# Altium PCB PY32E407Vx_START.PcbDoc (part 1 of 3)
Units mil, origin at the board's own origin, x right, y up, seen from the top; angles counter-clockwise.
Board outline 5249.65 x 2929.09 mil, 4 copper layers (Top Layer, GND, POWER, Bottom Layer); 239 components, 235 nets, 934 pads, 637 vias.
Unrouted connection lines stored in the file: 84.
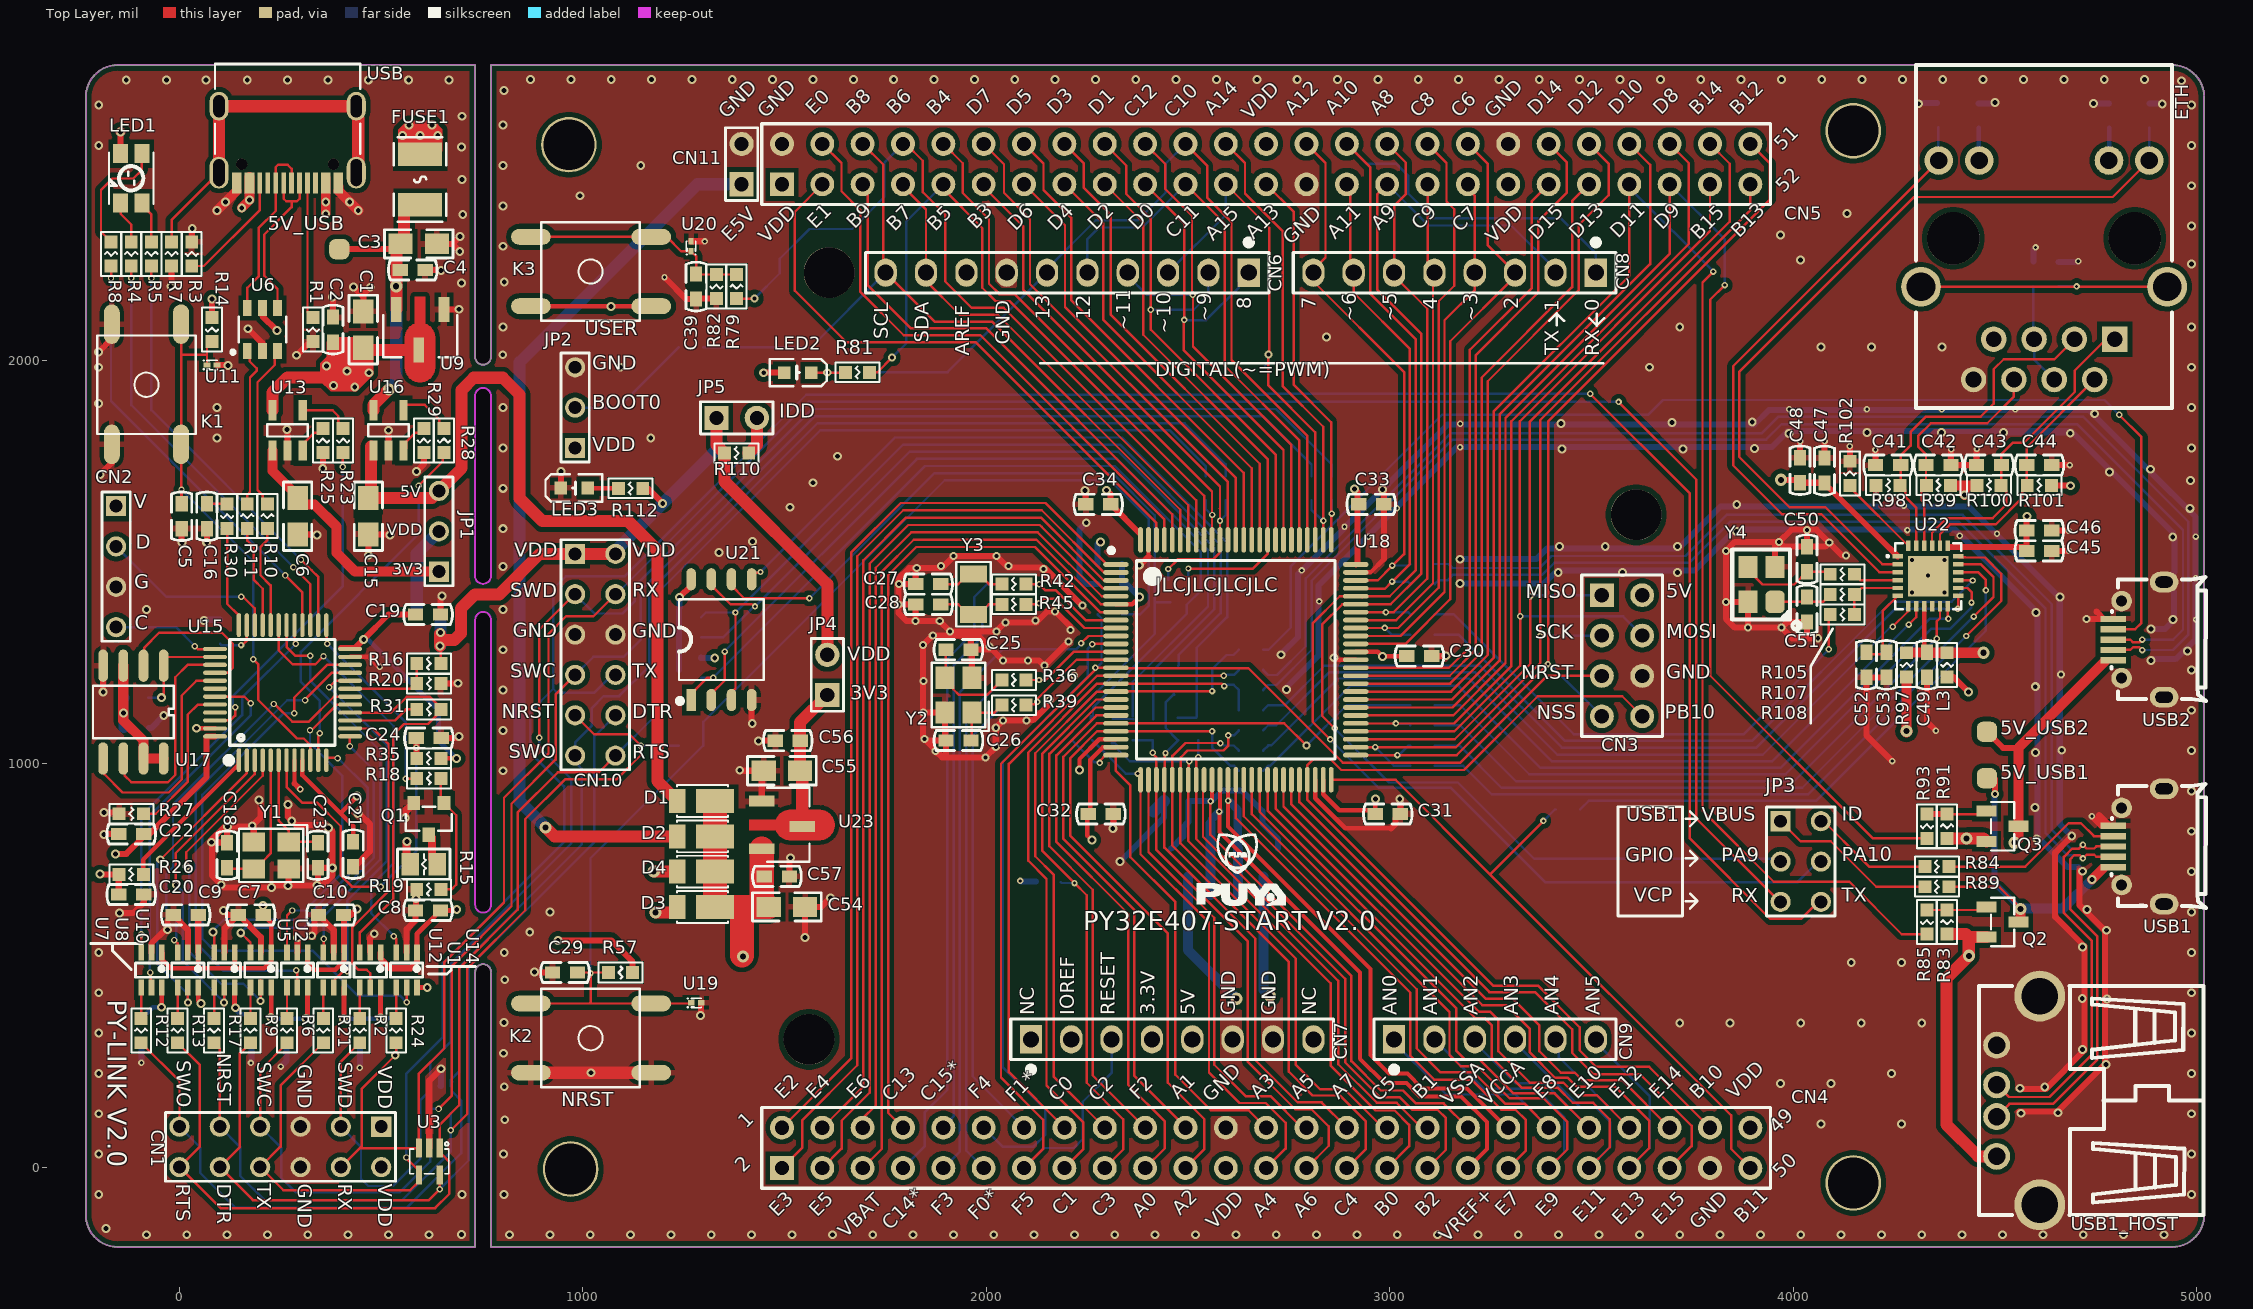
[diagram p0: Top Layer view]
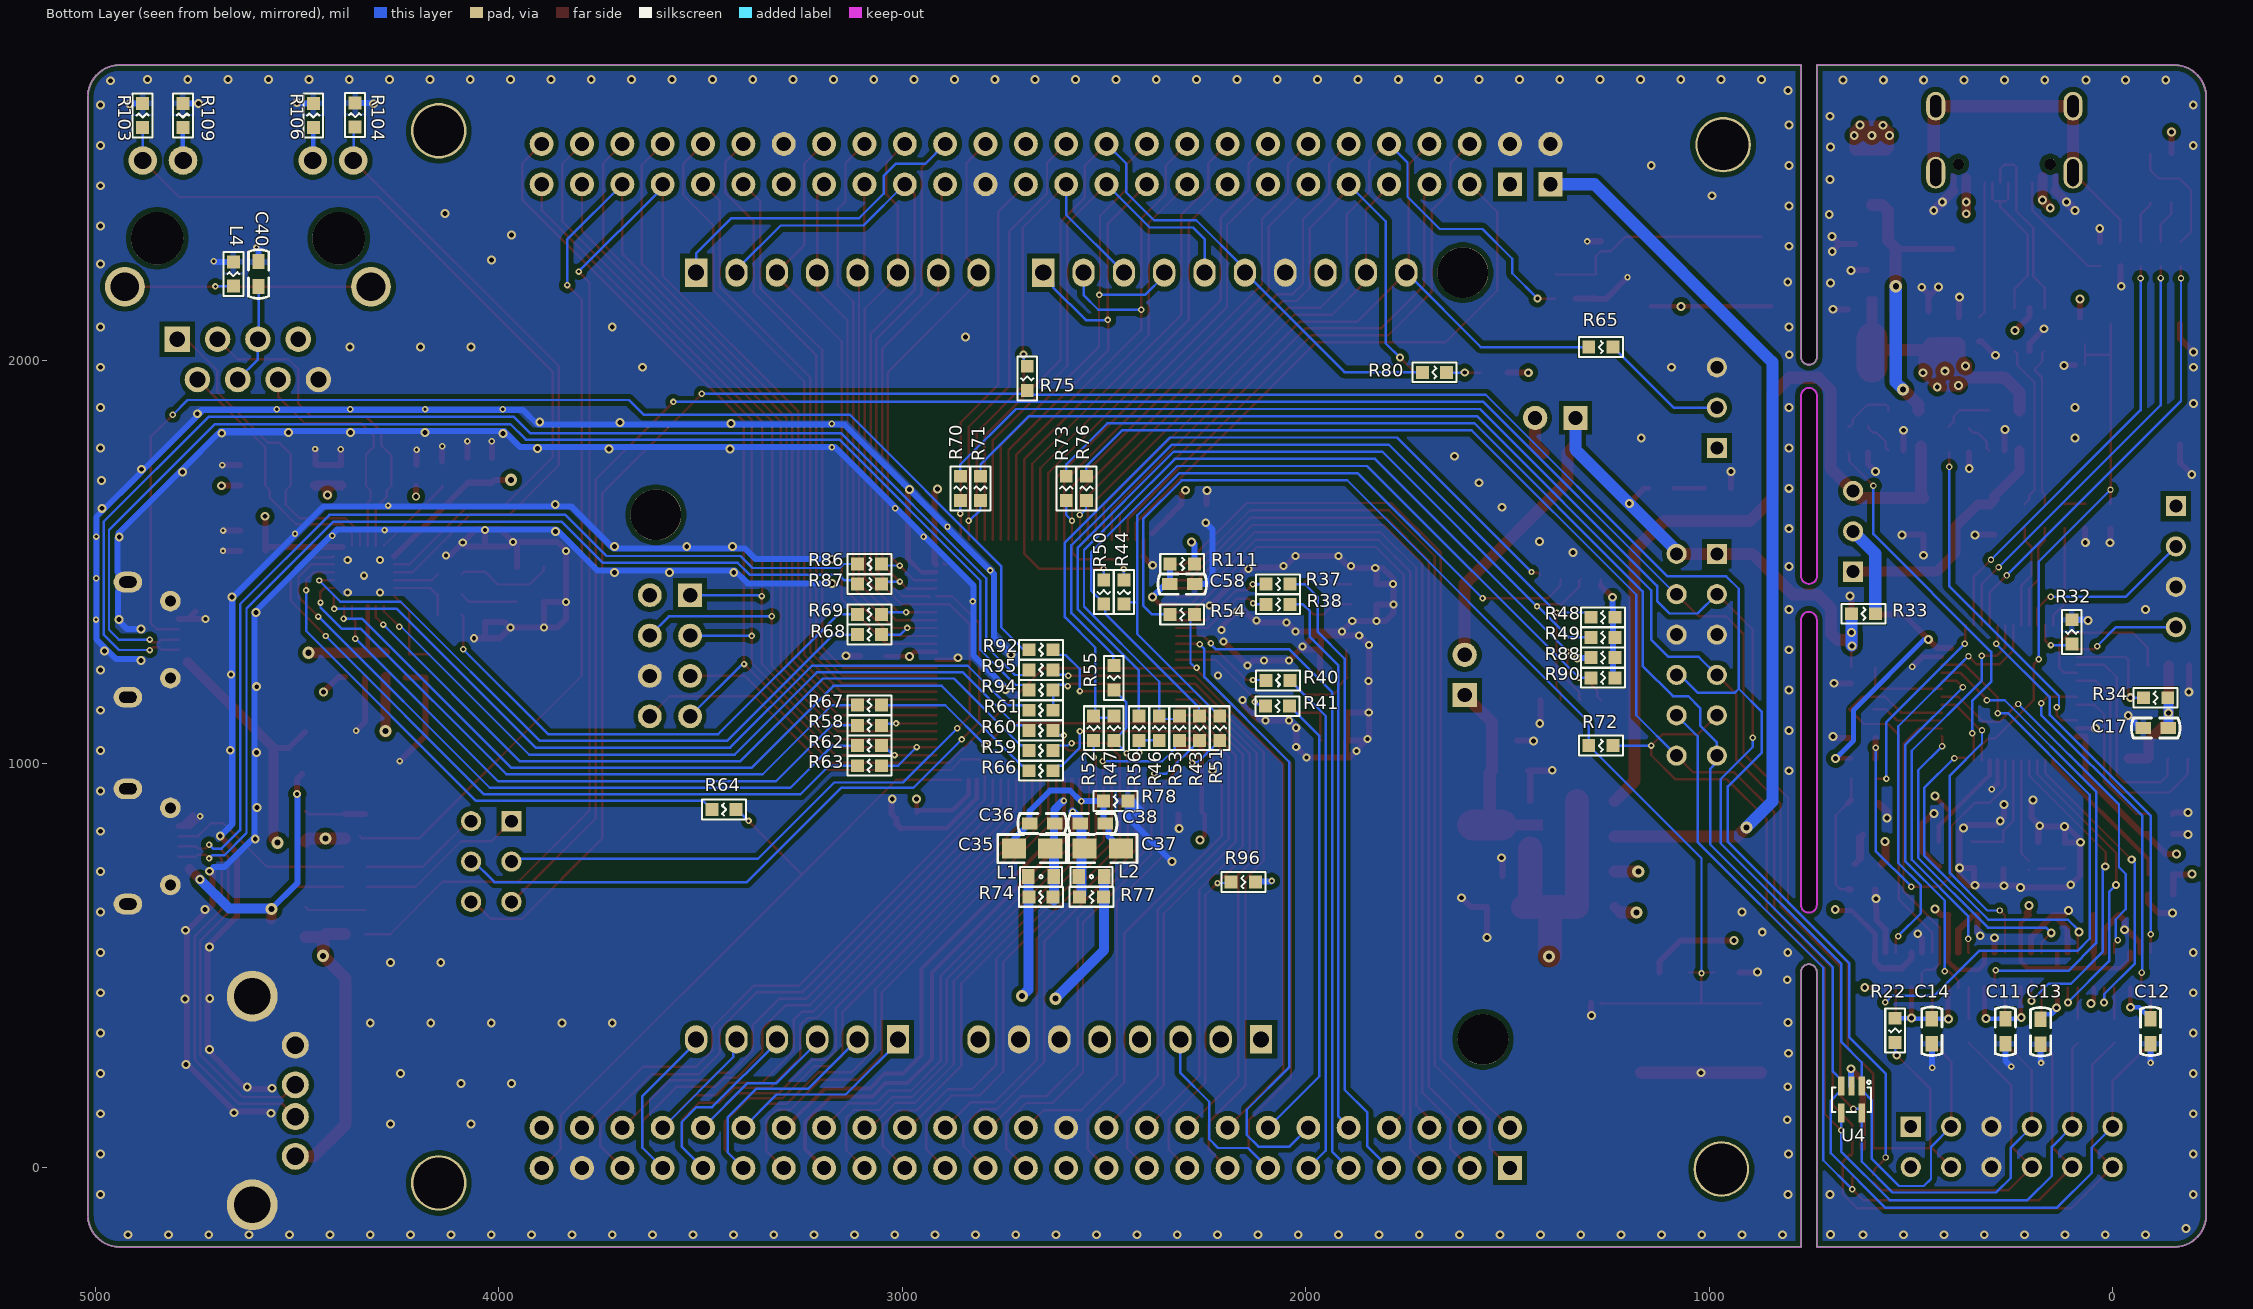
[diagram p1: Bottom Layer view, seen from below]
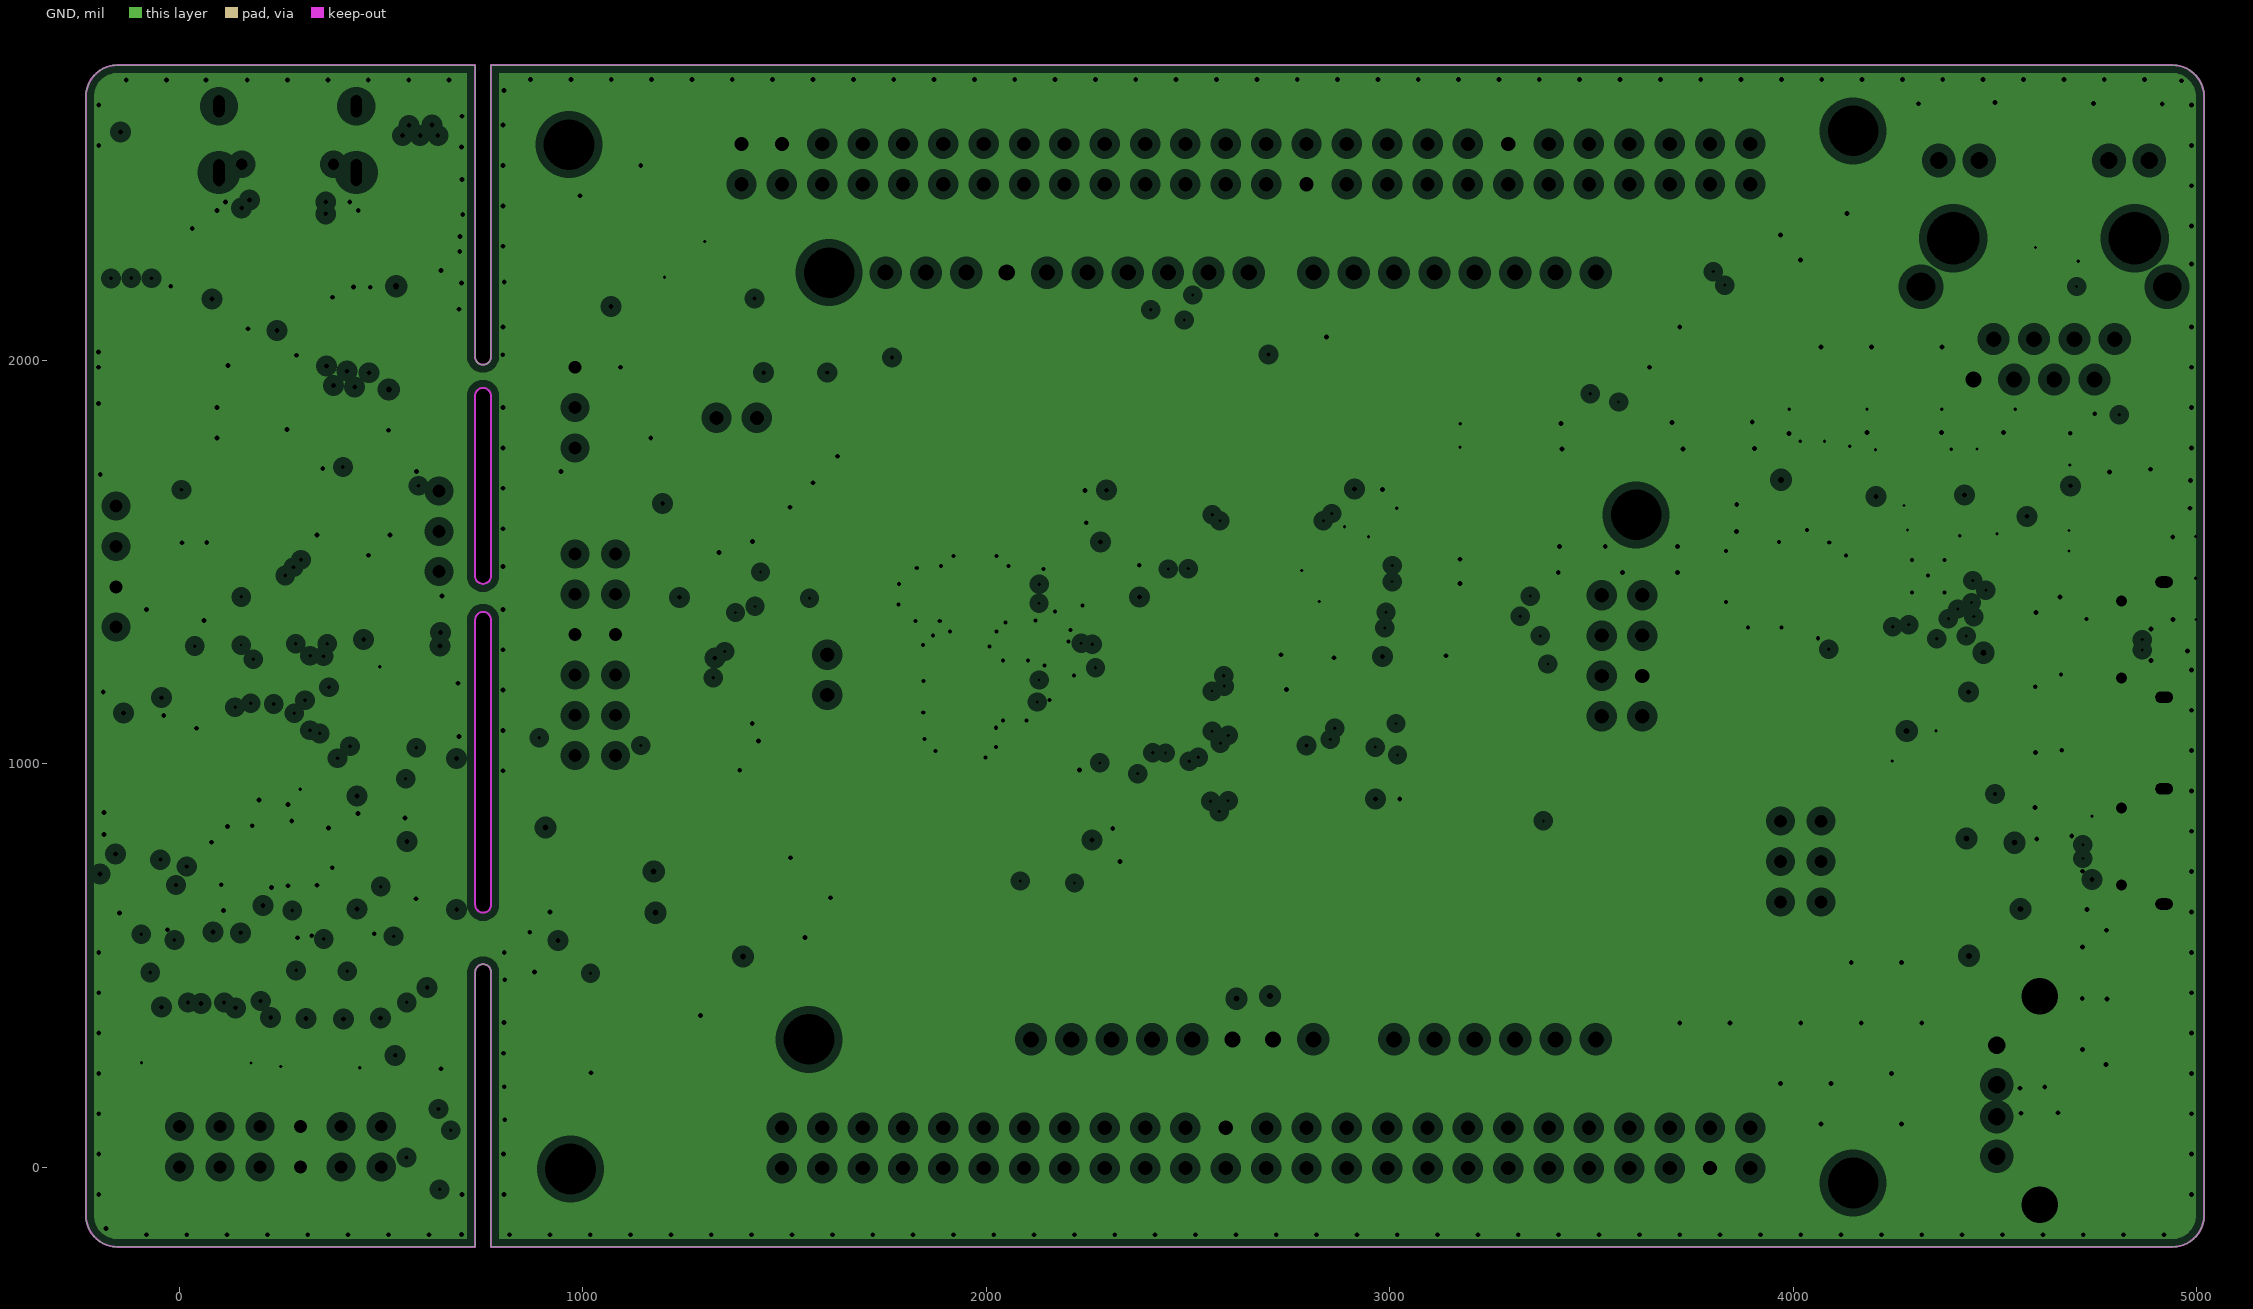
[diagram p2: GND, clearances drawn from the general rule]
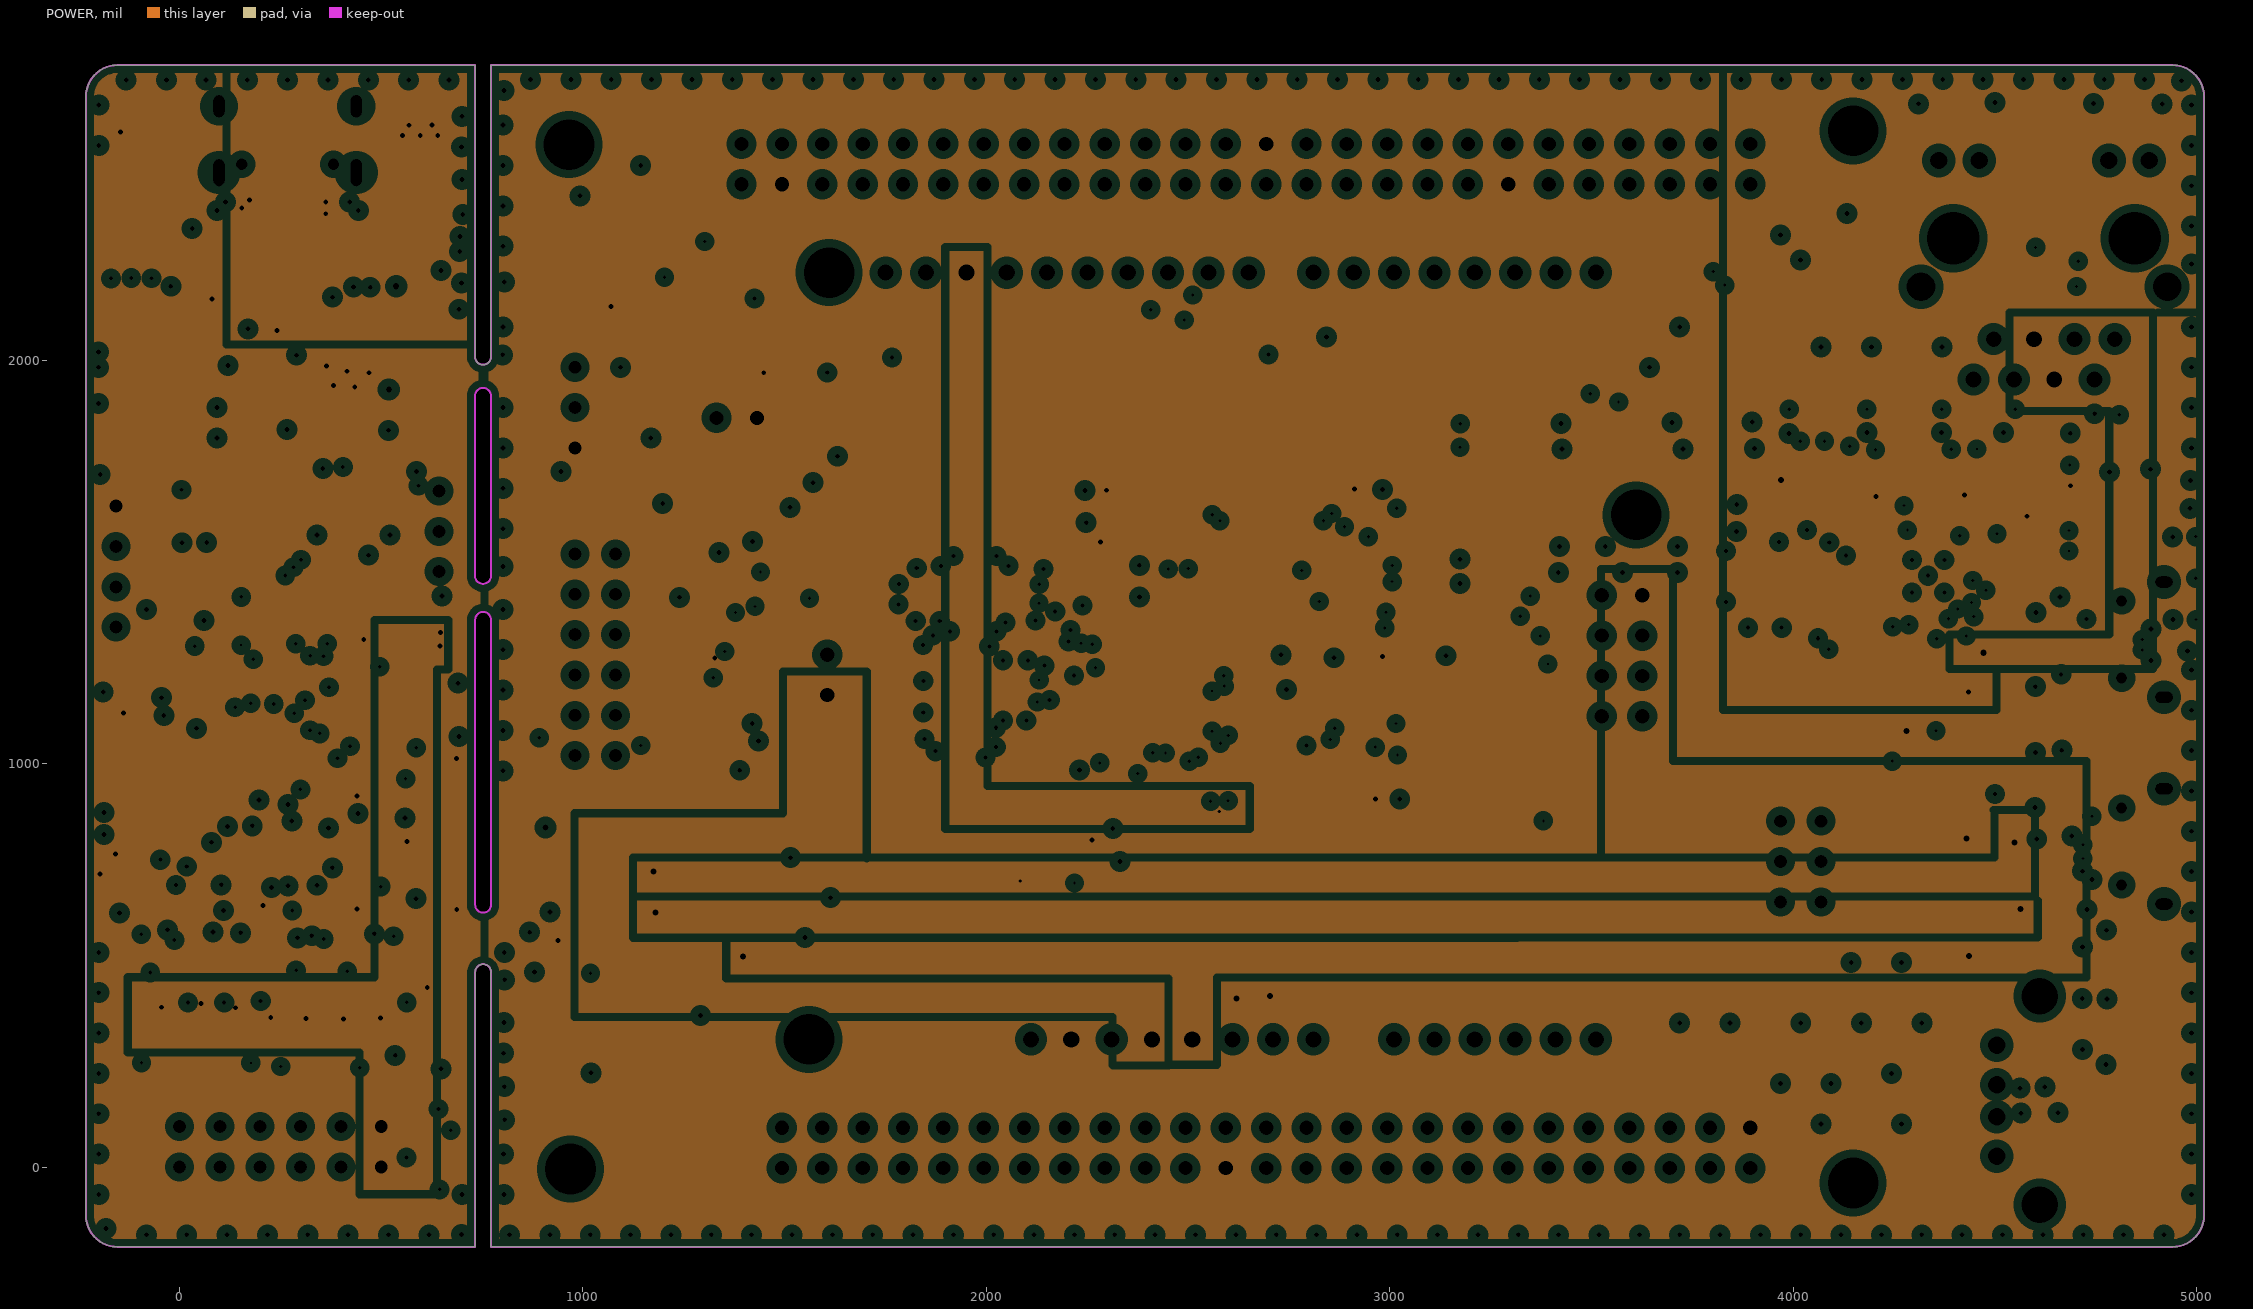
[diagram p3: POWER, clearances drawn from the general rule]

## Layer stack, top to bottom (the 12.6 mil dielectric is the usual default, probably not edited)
Top Solder: solder mask 0.4, Solder Resist, Dk 3.5
Top Layer: signal copper 1.4
Dielectric 2: prepreg 12.6, PP-006, Dk 4.1
GND: plane copper 1.378, net GND
Dielectric5: dielectric 12.6, FR-4, Dk 4.8
POWER: plane copper 1.378, net (Multiple Nets)
Dielectric4: dielectric 12.6, FR-4, Dk 4.8
Bottom Layer: signal copper 1.4
Bottom Solder: solder mask 0.4, Solder Resist, Dk 3.5

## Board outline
-153.26,-198 cw(c-153.26,-119.26) -232,-119.26 -232,2652.35 cw(c-153.26,2652.35) -153.26,2731.09 732.57,2731.09 732.57,2008.08 ccw(c752.25,2008.08) 771.94,2008.08 771.94,2731.09 4938.71,2731.09 cw(c4938.71,2652.35) 5017.45,2652.35 5017.65,2652.35 5017.65,-119.26 5017.61,-119.26 cw(c4938.87,-119.26) 4938.87,-198 772,-198 771.94,-198 771.94,483.05 772.29,483.05 ccw(c752.61,483.05) 732.92,483.05 732.57,483.05 732.57,-198
cut-out: 732.92,650.05 ccw(c752.61,650.05) 772.29,650.05 771.94,650.05 771.94,1356.05 772.29,1356.05 ccw(c752.61,1356.05) 732.92,1356.05 732.57,1357.05
cut-out: 732.57,1465.05 ccw(c752.25,1465.05) 771.94,1465.05 771.94,1911.05 ccw(c752.25,1911.05) 732.57,1911.05

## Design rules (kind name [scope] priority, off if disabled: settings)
Clearance [All] p1: gap=6 ignorepadtopadclearanceinfootprint=FALSE
ComponentClearance [All] p1 off: gap=10 collisioncheckmode=3 verticalgap=10 showdistances=FALSE
DiffPairsRouting DiffPairsRouting_2 [InDifferentialPair ('USB1')] p1: maxlimit=10 minlimit=10 mostfreqgap=10 toplayer_minwidth=15 toplayer_maxwidth=15 toplayer_prefwidth=15 bottomlayer_minwidth=15 bottomlayer_maxwidth=15 bottomlayer_prefwidth=15 maxuncoupledlength=500
DiffPairsRouting DiffPairsRouting_1 [InDifferentialPairClass('USB')] p2: maxlimit=10 minlimit=10 mostfreqgap=10 toplayer_minwidth=15 toplayer_maxwidth=15 toplayer_prefwidth=15 bottomlayer_minwidth=15 bottomlayer_maxwidth=15 bottomlayer_prefwidth=15 maxuncoupledlength=500
DiffPairsRouting DiffPair_DiffPairsRouting [All] p3: maxlimit=10 minlimit=10 mostfreqgap=10 toplayer_minwidth=15 toplayer_maxwidth=15 toplayer_prefwidth=15 bottomlayer_minwidth=15 bottomlayer_maxwidth=15 bottomlayer_prefwidth=15 maxuncoupledlength=500
DiffPairsRouting [All] p4: maxlimit=10 minlimit=10 mostfreqgap=10 toplayer_minwidth=15 toplayer_maxwidth=15 toplayer_prefwidth=15 bottomlayer_minwidth=15 bottomlayer_maxwidth=15 bottomlayer_prefwidth=15 maxuncoupledlength=500
HoleSize [All] p1: absolutevalues=TRUE maxlimit=300 minlimit=1 maxpercent=80.000 minpercent=20.000
HoleSize Testpoint [All] p2: absolutevalues=TRUE maxlimit=100 minlimit=1 maxpercent=80.000 minpercent=20.000
HoleSize TestPointUsage [All] p3: absolutevalues=TRUE maxlimit=100 minlimit=1 maxpercent=80.000 minpercent=20.000
MinimumSolderMaskSliver [All] p1: minsoldermaskwidth=0
PlaneClearance [All] p1: clearance=20
PlaneConnect [All] p1: planeconnectstyle=Direct reliefexpansion=20 reliefentries=4 reliefconductorwidth=10 reliefairgap=10
PolygonConnect "Polygon VIA" [IsVia] p1: connectstyle=Direct reliefconductorwidth=10 reliefentries=4 polygonreliefangle="90 Angle" airgapwidth=10
PolygonConnect [All] p2: thpad.connectstyle=Direct thpad.reliefconductorwidth=10 thpad.reliefentries=4 thpad.polygonreliefangle="90 Angle" thpad.airgapwidth=10 smdpad.connectstyle=Relief smdpad.reliefconductorwidth=15 smdpad.reliefentries=4 smdpad.polygonreliefangle="90 Angle" smdpad.airgapwidth=10 via.connectstyle=Direct via.reliefconductorwidth=10 via.reliefentries=4 via.polygonreliefangle="90 Angle" via.airgapwidth=10
RoutingVias [All] p1: holewidth=20 width=40 viastyle="Through Hole" minholewidth=20 minwidth=40 maxholewidth=20 maxwidth=40
SilkToSilkClearance [All] p1: silktosilkclearance=0
SilkToSolderMaskClearance [IsPad] p1: minsilkscreentomaskgap=0 clearancetoexposedcopper=TRUE
SolderMaskExpansion [All] p1: expansion=4 istentingtop=FALSE
SupplyNets "Schematic Supply Nets_18" [InNet('E_5V')] p1: voltage=0.000
SupplyNets "Schematic Supply Nets_17" [InNet('5V_USB1_START')] p2: voltage=0.000
SupplyNets "Schematic Supply Nets_16" [InNet('ETH_VDDA')] p3: voltage=0.000
SupplyNets "Schematic Supply Nets_15" [InNet('VCCA')] p4: voltage=0.000
SupplyNets "Schematic Supply Nets_14" [InNet('3V3')] p5: voltage=0.000
SupplyNets "Schematic Supply Nets_13" [InNet('VDD')] p6: voltage=0.000
SupplyNets "Schematic Supply Nets_12" [InNet('TVDD')] p7: voltage=0.000
SupplyNets "Schematic Supply Nets_11" [InNet('VREF+')] p8: voltage=0.000
SupplyNets "Schematic Supply Nets_10" [InNet('GND')] p9: voltage=0.000
SupplyNets "Schematic Supply Nets_9" [InNet('VBAT')] p10: voltage=0.000
SupplyNets "Schematic Supply Nets_8" [InNet('5V_USB_CHGR')] p11: voltage=0.000
SupplyNets "Schematic Supply Nets_7" [InNet('5V_USB2_START')] p12: voltage=0.000
SupplyNets "Schematic Supply Nets_6" [InNet('5V')] p13: voltage=0.000
SupplyNets "Schematic Supply Nets_5" [InNet('3V3_USB_PYLK')] p14: voltage=0.000
SupplyNets "Schematic Supply Nets_4" [InNet('VDD_FLASH')] p15: voltage=0.000
SupplyNets "Schematic Supply Nets_3" [InNet('3V3_PYLK')] p16: voltage=0.000
SupplyNets "Schematic Supply Nets_2" [InNet('5V_USB_PYLK')] p17: voltage=0.000
SupplyNets "Schematic Supply Nets_1" [InNet('VSSA')] p18: voltage=0.000
SupplyNets "Schematic Supply Nets" [InNet('ETH_VDD')] p19: voltage=0.000
Width [All] p1: maxlimit=80 minlimit=6 preferedwidth=6
22 further rules are at their usual default settings.

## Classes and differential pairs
component class Designator: C39 K3 LED2 Q2 Q3 R82 R83 R84 R85 R86 R87 R88 R89 R90 R91 R92 R93 R94 R95 R96 U20 U21 USB1 USB1_HOST USB2
net class PF[0..5]: PF0 PF1 PF2 PF3 PF4 PF5
net class PE[0..15]: PE0 PE1 PE2 PE3 PE4 PE5 PE6 PE7 PE8 PE9 PE10 PE11 PE12 PE13 PE14 PE15
net class PD[0..15]: PD0 PD1 PD2 PD3 PD4 PD5 PD6 PD7 PD8 PD9 PD10 PD11 PD12 PD13 PD14 PD15
net class PC[0..15]: PC0 PC1 PC2 PC3 PC4 PC5 PC6 PC7 PC8 PC9 PC10 PC11 PC12 PC13 PC14 PC15
net class PB[0..15]: PB0 PB1 PB2 PB3 PB4 PB5 PB6 PB7 PB8 PB9 PB10 PB11 PB12 PB13 PB14 PB15
net class PA[0..15]: PA0 PA1 PA2 PA3 PA4 PA5 PA6 PA7 PA8 PA9 PA10 PA11 PA12 PA13 PA14 PA15

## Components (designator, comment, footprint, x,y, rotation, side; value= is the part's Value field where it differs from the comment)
5V_USB "TP_SIN" TP_SIN 396.1,2274.79 r0 top
5V_USB1 "TP_SIN" TP_SIN 4479.3,963.69 r0 top
5V_USB2 "TP_SIN" TP_SIN 4479.3,1078.69 r0 top
C1 "10uF" C0805 455.5,2075.5 r270 top
C2 "100nF" C0603 380.5,2075.5 r270 top
C3 "10uF" C0805 593,2288 r180 top
C4 "100nF" C0603 578.1,2223.2 r180 top
C5 "100nF" C0603 5.5,1613 r90 top
C6 "10uF" C0805 293,1613 r90 top
C7 "100nF" C0603 176.6,624.9 r0 top value=104
C8 "100nF" C0603 616,636.09 r0 top value=104
C9 "100nF" C0603 15.3,624.9 r0 top value=104
C10 "100nF" C0603 375.5,624.9 r0 top value=104
C11 "100nF" C0603 265.7,336.7 r90 bottom value=104
C12 "100nF" C0603 -94.3,336.6 r90 bottom value=104
C13 "100nF" C0603 178.2,335.3 r90 bottom value=104
C14 "100nF" C0603 447.9,336.7 r90 bottom value=104
C15 "10uF" C0805 468,1613 r90 top
C16 "100nF" C0603 68,1613 r90 top
C17 "100nF" C0603 -107,1088 r180 bottom value=104
C18 "22pF" C0603 118,772.6 r270 top
C19 "100nF" C0603 616,1369.3 r180 top value=104
C20 "100nF" C0603 -119.5,675.5 r180 top value=104
C21 "100nF" C0603 430.5,775.5 r90 top value=104
C22 "100nF" C0603 -119.5,825.5 r0 top value=104
C23 "22pF" C0603 343,772.6 r90 top
C24 "100nF" C0603 618,1063 r180 top value=104
C25 "22pF" C0603 1930.5,1282.09 r180 top
C26 "22pF" C0603 1930.5,1057.09 r0 top
C27 "22pF" C0603 1855.5,1444.59 r0 top
C28 "22pF" C0603 1855.5,1394.59 r0 top
C29 "100nF" C0603 955.5,482.09 r0 top
C30 "100nF" C0603 3072.8,1266.29 r180 top
C31 "100nF" C0603 2994.61,875.01 r180 top
C32 "100nF" C0603 2283.54,875.01 r180 top
C33 "100nF" C0603 2953.6,1642.49 r180 top
C34 "100nF" C0603 2276.7,1642.49 r0 top
C35 "1uF" C0805 2677.6,789.09 r180 bottom
C36 "100nF" C0603 2652.6,851.59 r180 bottom
C37 "1uF" C0805 2502.6,789.09 r0 bottom
C38 "100nF" C0603 2527.6,851.59 r0 bottom
C39 "100nF" C0603 1280.5,2182.09 r90 top
C40 "100nF" C0603 4594.5,2213.09 r270 bottom
C41 "NC/10pF" C0603 4234.4,1739.59 r0 top
C42 "NC/10pF" C0603 4359.4,1739.59 r180 top
C43 "NC/10pF" C0603 4484.4,1739.59 r0 top
C44 "NC/10pF" C0603 4609.4,1739.59 r180 top
C45 "100nF" C0603 4609,1527.09 r180 top
C46 "100nF" C0603 4609,1577.09 r180 top
C47 "10uF" C0603 4076.7,1726.19 r270 top
C48 "100nF" C0603 4016.2,1726.89 r270 top
C49 "100nF" C0603 4330.5,1244.59 r90 top
C50 "22pF" C0603 4033.5,1506.59 r90 top
C51 "22pF" C0603 4033.5,1381.59 r90 top
C52 "10uF" C0603 4180.5,1244.59 r90 top
C53 "100nF" C0603 4230.5,1244.59 r90 top
C54 "10uF" C0805 1505.5,644.59 r180 top
C55 "10uF" C0805 1493,982.09 r0 top
C56 "0.1uF/50V" C0603CAP 1476.4,1056.59 r90 top
C57 "0.1uF/50V" C0603CAP 1511.6,720.29 r270 top value=2.2uF
C58 "100nF" C0603 2305.5,1444.59 r0 bottom
CN1 "CON6x2" CON6X2 500,0 r270 top locked
CN2 "CON4" CON4 -157,1638 r270 top
CN3 "Header 4X2" HDR2X4 3525.12,1417.14 r270 top locked
CN4 "Header 25X2" HDR2X25 1493.11,-2.45 r0 top locked
CN5 "Header 25X2" HDR2X25 1493.11,2435.55 r0 top locked
CN6 "Header 10" 1*10P_FEMALE 2650.11,2216.55 r180 top locked
CN7 "Header 8" 1*8P_FEMALE 2110.11,316.55 r0 top locked
CN8 "Header 8" 1*8P_FEMALE 3510.11,2216.55 r180 top locked
CN9 "Header 6" 1*6P_FEMALE 3010.11,316.55 r0 top locked
CN10 "CON6x2" CON6X2 1080.5,1519.59 r0 top locked
CN11 "CON2" CON2 1393.11,2435.55 r90 top locked
D1 "DFLS130L-7" POWERDI-123_L2.8-W1.8-LS3.7-RD 1280.5,907.09 r180 top
D2 "DFLS130L-7" POWERDI-123_L2.8-W1.8-LS3.7-RD 1280.5,819.59 r180 top
D3 "DFLS130L-7" POWERDI-123_L2.8-W1.8-LS3.7-RD 1280.5,644.59 r180 top
D4 "DFLS130L-7" POWERDI-123_L2.8-W1.8-LS3.7-RD 1280.5,732.09 r180 top
ETH "HR911105A" RJ45-TH_HR911105A 4621,2223.09 r180 top locked
FUSE1 "BSMD1206-050-6V" SDM1210P005TF 618,2450.5 r270 top
JP1 "CON3" CON3 643,1475.5 r90 top
JP2 "CON3" CON3 980.5,1782.09 r90 top
JP3 "CON3x2" CON3x2 4068,857.09 r0 top
JP4 "CON2" CON2 1605.5,1169.59 r90 top
JP5 "CON2" CON2 1330.89,1856.71 r0 top
K1 "1TS002B-2600-5001_key" SWITCH -82,1938 r90 top
K2 "1TS002B-2600-5001_key" SWITCH 1018,319.59 r0 top locked
K3 "1TS002B-2600-5001_key" SWITCH 1018,2219.59 r0 top locked
L1 "BEAD" L0603 2655.5,719.59 r180 bottom value=600R@100MHz
L2 "BEAD" L0603 2530.5,719.59 r0 bottom value=600R@100MHz
L3 "330@100MHz" R0603 4380.5,1244.59 r90 top
L4 "330@100MHz" R0603 4657,2213.09 r270 bottom
LED1 "MHPA3528RGBCT" LED-ARRAY-SMD_4P-L3.5-W2.8-TL -119.5,2450.5 r90 top
LED2 "GREEN" 0603_LED 1518,1969.59 r180 top
LED3 "RED" 0603_LED 993,1682.09 r0 top
Q1 "2302" SOT23 618,863 r0 top value=SI2302
Q2 "SI2301" SOT-23-3_L2.9-W1.3-P1.90-LS2.4-BR 4518,607.09 r180 top
Q3 "SI2301" SOT-23-3_L2.9-W1.3-P1.90-LS2.4-BR 4518,844.59 r180 top
R1 "5.1K" R0603 330.5,2075.5 r90 top
R2 "27R" R0603 446.71,338 r270 top
R3 "5.1K" R0603 30.5,2263 r90 top
R4 "680R" R0603 -119.5,2263 r270 top
R5 "680R" R0603 -69.5,2263 r270 top
R6 "27R" R0603 266.14,338 r270 top
R7 "1M" R0603 -19.5,2263 r270 top
R8 "680R" R0603 -169.5,2263 r270 top
R9 "27R" R0603 175.86,338 r270 top
R10 "27R" R0603 218,1613 r270 top
R11 "27R" R0603 168,1613 r270 top
R12 "27R" R0603 -95,338 r270 top
R13 "27R" R0603 -4.71,338 r270 top
R14 "10K" R0603 80.5,2075.5 r90 top
R15 "100R" R0805 605.5,750.5 r180 top
R16 "20K" R0603 618,1248 r0 top
R17 "27R" R0603 85.57,338 r270 top
R18 "100R" R0603 618,963 r180 top
R19 "100K" R0603 618,688 r0 top
R20 "10K" R0603 618,1198 r180 top
R21 "27R" R0603 356.43,338 r270 top
R22 "4.7K" R0603 538.7,338.7 r90 bottom
R23 "4.7K" R0603 405.5,1800.5 r90 top
R24 "27R" R0603 537,338 r270 top
R25 "16K" R0603 355.5,1800.5 r90 top
R26 "0R/NC" R0603 -119.5,725.5 r0 top
R27 "10K" R0603 -119.5,875.5 r180 top
R28 "4.7K" R0603 655.5,1800.5 r90 top
R29 "16K" R0603 605.5,1800.5 r90 top
R30 "0R/NC" R0603 118,1613 r90 top
R31 "100R" R0603 618,1134.09 r180 top
R32 "0R/NC" R0603 100.8,1326.39 r90 bottom
R33 "0R" R0603 617.1,1371.3 r0 bottom
R34 "100K" R0603 -107,1163 r180 bottom
R35 "10K" R0603 618,1013 r0 top
R36 "0R" R0603 2068,1207.09 r0 top
R37 "0R" R0603 2068,1444.59 r0 bottom
R38 "0R" R0603 2068,1394.59 r0 bottom
R39 "0R" R0603 2068,1144.59 r0 top
R40 "0R" R0603 2068.2,1205.99 r0 bottom
R41 "0R" R0603 2069.3,1142.19 r0 bottom
R42 "0R" R0603 2068,1444.59 r0 top
R43 "0R" R0603 2262.5,1087.5 r270 bottom
R44 "0R" R0603 2450,1425 r90 bottom
R45 "0R" R0603 2068,1394.59 r0 top
R46 "0R" R0603 2362.5,1087.5 r270 bottom
R47 "0R" R0603 2475,1087.5 r270 bottom
R48 "0R/NC" R0603 1262.5,1362.5 r180 bottom
R49 "0R/NC" R0603 1262.5,1312.5 r180 bottom
R50 "0R" R0603 2500,1425 r90 bottom
R51 "0R" R0603 2212.5,1087.5 r270 bottom
R52 "0R" R0603 2525,1087.5 r270 bottom
R53 "0R" R0603 2312.5,1087.5 r270 bottom
R54 "0R" R0603 2305.5,1369.59 r180 bottom
R55 "0R" R0603 2475,1212.5 r270 bottom
R56 "0R" R0603 2412.5,1087.5 r270 bottom
R57 "10K" R0603 1093,482.09 r180 top
R58 "0R" R0603 3080.5,1094.59 r180 bottom
R59 "0R" R0603 2655.5,1032.09 r180 bottom
R60 "0R" R0603 2655.5,1082.09 r180 bottom
R61 "0R" R0603 2655.5,1132.09 r180 bottom
R62 "0R" R0603 3080.5,1044.59 r180 bottom
R63 "0R" R0603 3080.5,994.59 r180 bottom
R64 "0R" R0603 3441.05,886.09 r180 bottom
R65 "10K" R0603 1268,2032.09 r0 bottom
R66 "0R" R0603 2655.5,982.09 r180 bottom
R67 "0R" R0603 3080.5,1144.59 r180 bottom
R68 "0R" R0603 3080.5,1319.59 r180 bottom
R69 "0R" R0603 3080.5,1369.59 r180 bottom
R70 "0R" R0603 2855.5,1682.09 r270 bottom
R71 "0R" R0603 2805.5,1682.09 r270 bottom
R72 "0R" R0603 1268,1044.59 r0 bottom
R73 "0R" R0603 2593,1682.09 r270 bottom
R74 "0R/NC" R0603 2655.5,669.59 r180 bottom
R75 "0R" R0603 2689.6,1954.69 r90 bottom
R76 "0R" R0603 2543,1682.09 r270 bottom
R77 "0R/NC" R0603 2530.5,669.59 r0 bottom
R78 "0R" R0603 2470.4,907.19 r180 bottom
R79 "0R" R0603 1380.5,2182.09 r270 top
R80 "680R/NC" R0603 1680.5,1969.59 r0 bottom
R81 "680R" R0603 1680.5,1969.59 r0 top
R82 "1.5K" R0603 1330.5,2182.09 r90 top
R83 "10K" R0603 4380.5,607.09 r270 top
R84 "1K" R0603 4355.5,744.59 r0 top
R85 "470R" R0603 4330.5,607.09 r90 top
R86 "22R" R0603 3080.5,1494.59 r0 bottom
R87 "22R" R0603 3080.5,1444.59 r0 bottom
R88 "0R" R0603 1262.5,1262.5 r180 bottom
R89 "10K" R0603 4355.5,694.59 r0 top
R90 "100K" R0603 1262.5,1212.5 r180 bottom
R91 "10K" R0603 4380.5,844.59 r270 top
R92 "1K" R0603 2655.5,1282.09 r0 bottom
R93 "470R" R0603 4330.5,844.59 r90 top
R94 "22R" R0603 2655.5,1182.09 r0 bottom
R95 "22R" R0603 2655.5,1232.09 r0 bottom
R96 "10K" R0603 2154.2,706.19 r180 bottom
R97 "0R" RES0603 4280.5,1244.59 r90 top
R98 "49.9R" R0603 4234.4,1689.59 r180 top
R99 "49.9R" R0603 4359.4,1689.59 r0 top
R100 "49.9R" R0603 4484.4,1689.59 r180 top
R101 "49.9R" R0603 4609.4,1689.59 r0 top
R102 "12.1K" R0603 4139.7,1719.09 r90 top
R103 "4.7K" R0603 4882,2606.09 r270 bottom
R104 "4.7K" R0603 4355.5,2607.09 r270 bottom
R105 "0R" R0603 4121,1469.09 r0 top
R106 "270" R0603 4459,2606.09 r270 bottom
R107 "0R" R0603 4121,1419.09 r0 top
R108 "0R" R0603 4121,1369.09 r180 top
R109 "270" R0603 4782,2606.09 r270 bottom
R110 "0R" R0603 1380.89,1769.21 r0 top
R111 "0R" R0603 2305.5,1494.59 r0 bottom
R112 "680R" R0603 1118,1682.09 r0 top
U1 "74LVC1T45DW" SOT363 472.69,488.04 r180 top
U2 "74LVC1T45DW" SOT363 292,488.04 r180 top
U3 "ESD_6V1" ESD_SOT323-5L 619,14 r180 top value=ESDALC6V1W5
U4 "ESD_6V1" ESD_SOT323-5L 647,167 r0 bottom value=ESDALC6V1W5
U5 "74LVC1T45DW" SOT363 201.66,488.04 r180 top
U6 "USBLC6-2SC6" SOT23-6 205.5,2075.5 r180 top
U7 "74LVC1T45DW" SOT363 -69.37,488.04 r180 top
U8 "74LVC1T45DW" SOT363 20.97,488.04 r180 top
U9 "LM1117-3.3" LM1117-3.3 655.5,2125.5 r90 top
U10 "74LVC1T45DW" SOT363 111.31,488.04 r180 top
U11 "ESD-TRANSIL" ESD_ST0201 80.5,1988 r0 top value=ESDALC6V1-1U2
U12 "74LVC1T45DW" SOT363 382.34,488.04 r180 top
U13 "MT9700" SOT23-5 268,1825.5 r0 top
U14 "74LVC1T45DW" SOT363 563.03,488.04 r180 top
U15 "PY32F072C1xT" LQFP-48_L7.0-W7.0-P0.50-LS9.0-BL 255.5,1175.69 r0 top locked
U16 "MT9700" SOT23-5 518,1825.5 r0 top
U17 "P25Q64H" SOP-8P -114.3,1127.5 r180 top value=SST25VF020B
U18 "PY32E407Vx" LQFP-100_L14.0-W14.0-P0.50-LS16.0-BL 2618,1257.09 r270 top locked
U19 "ESD-TRANSIL" ESD_ST0201 1280.5,407.09 r0 top value=ESDALC6V1-1U2
U20 "ESD-TRANSIL" ESD_ST0201 1268,2282.09 r90 top value=ESDALC6V1-1U2
U21 "P25Q128H" SOP8W_L 1343,1307.09 r90 top locked
U22 "LAN8720A-CP-TR" QFN-24_L4.0-W4.0-P0.50-BL-EP2.6 4333.5,1464.59 r270 top
U23 "LM1117-3.3" LM1117-3.3 1443,907.09 r180 top
USB "KH-TYPE-C-16P" USB-C-SMD_KH-TYPE-C-16P 268,2534 r180 top
USB1 "Micro-B" MICRO-USB-SMD_MICROXNJ 4855.5,794.59 r90 top locked
USB1_HOST "Type-A" USB-A-TH_AF-WJDG 4557,165.09 r90 top locked
USB2 "Micro-B" MICRO-USB-SMD_MICROXNJ 4855.5,1307.09 r90 top locked
Y1 "24MHz" CRYSTAL-SMD_4P-L3.2-W2.5-BL 227.3,772.6 r180 top
Y2 "24MHz" CRYSTAL-SMD_4P-L3.2-W2.5-BL 1930.5,1169.59 r90 top
Y3 "32.768KHz" CRYSTAL-SMD_L3.2-W1.5-1 1968,1419.59 r90 top value=32.768kHz
Y4 "25MHz" SMD-3225_4P 3921,1444.09 r90 top

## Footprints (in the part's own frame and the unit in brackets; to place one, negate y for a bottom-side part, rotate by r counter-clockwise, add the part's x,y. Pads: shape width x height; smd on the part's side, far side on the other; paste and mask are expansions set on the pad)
1*6P_FEMALE [mil]
  rect 55x70 hole 40: 1(0,0)
  oval 55x70 hole 40: 2(100,0) 3(200,0) 4(300,0) 5(400,0) 6(500,0)
  silkscreen extent -50,-82 550,50
1*8P_FEMALE [mil]
  rect 55x70 hole 40: 1(0,0)
  oval 55x70 hole 40: 2(100,0) 3(200,0) 4(300,0) 5(400,0) 6(500,0) 7(600,0) 8(700,0)
  silkscreen extent -50,-82 750,50
1*10P_FEMALE [mil]
  rect 55x70 hole 40: 1(0,0)
  oval 55x70 hole 40: 2(100,0) 3(200,0) 4(300,0) 5(400,0) 6(500,0) 7(600,0) 8(700,0) 9(800,0) 10(900,0)
  silkscreen extent -50,-82 950,50
0603_LED [mil]
  rect 31.5x31.5 smd: 1(19,1) 2(-48,1)
  silkscreen extent -86,-33 55,35
C0603 [mil]
  rect 38x30 smd: 1(-31,0) 2(31,0)
  silkscreen extent -60,-25 60,25
C0603CAP [mil]
  rect 30x38 smd: 1(0,0) 2(0,-62)
  silkscreen extent -25,-91 25,29
C0805 [mil]
  rect 60x50 smd: 1(-45,0) 2(45,0)
  silkscreen extent -85,-35 85,35
CON2 [mil]
  rect 60x60 hole 35: 1(0,0)
  round 60 hole 35: 2(100,0)
  silkscreen extent -40,-40 140,40
CON3 [mil]
  rect 50x50 hole 32: 1(0,0)
  round 50 hole 32: 2(100,0) 3(200,0)
  silkscreen extent -35,-35 235,35
CON3x2 [mil]
  rect 50x50 hole 32: 1(-100,0)
  round 50 hole 32: 2(0,0) 3(-100,-100) 4(0,-100) 5(-100,-200) 6(0,-200)
  silkscreen extent -135,-235 35,35
CON4 [mil]
  rect 50x50 hole 32: 1(0,0)
  round 50 hole 32: 2(100,0) 3(200,0) 4(300,0)
  silkscreen extent -35,-35 335,35
CON6X2 [mil]
  rect 50x50 hole 32: 1(-100,0)
  round 50 hole 32: 2(0,0) 3(-100,-100) 4(0,-100) 5(-100,-200) 6(0,-200) 7(-100,-300) 8(0,-300) 9(-100,-400) 10(0,-400) 11(-100,-500) 12(0,-500)
  silkscreen extent -135,-535 35,35
CRYSTAL-SMD_4P-L3.2-W2.5-BL [mm]
  rect 1.4x1.2 smd: 1(-1.1,-0.85) 2(1.1,-0.85) 3(1.1,0.85) 4(-1.1,0.85)
  silkscreen extent -2.26,-1.91 2.03,1.68
CRYSTAL-SMD_L3.2-W1.5-1 [mm]
  rect 1.05x1.7 smd: 1(-1.275,0) 2(1.275,0)
  silkscreen extent -2.03,-1.08 2.03,1.08
ESD_SOT323-5L [mm]
  rect 0.4x1.2 smd mask+0.05: 1(-0.65,-0.85) 2(0,-0.85) 3(0.65,-0.85) 4(0.65,0.85) 5(-0.65,0.85)
  silkscreen extent -1.23,-1.21 1.23,0.77, body extent -1.15,-1.05 1.15,1.05, height 1.1
ESD_ST0201 [mm]
  rect 0.425x0.33 smd mask+0.05: 1(-0.312,0) 2(0.312,0)
  silkscreen extent -0.55,-0.3 0.33,0.3, body extent -0.34,-0.18 0.34,0.18, height 0.34
HDR2X4 [mm] "Connector; Header; 4x2 Position"
  rect 1.5x1.5 hole 0.9: 1(0,0)
  round 1.5 hole 0.9: 2(0,2.54) 3(2.54,0) 4(2.54,2.54) 5(5.08,0) 6(5.08,2.54) 7(7.62,0) 8(7.62,2.54)
  silkscreen extent -1.27,-1.27 8.89,3.81
HDR2X25 [mm] "Connector; Header; 25x2 Position"
  rect 1.5x1.5 hole 0.9: 1(0,0)
  round 1.5 hole 0.9: 2(0,2.54) 3(2.54,0) 4(2.54,2.54) 5(5.08,0) 6(5.08,2.54) 7(7.62,0) 8(7.62,2.54) 9(10.16,0) 10(10.16,2.54) 11(12.7,0) 12(12.7,2.54) 13(15.24,0) 14(15.24,2.54) 15(17.78,0) 16(17.78,2.54) 17(20.32,0) 18(20.32,2.54) 19(22.86,0) 20(22.86,2.54) 21(25.4,0) 22(25.4,2.54) 23(27.94,0) 24(27.94,2.54) 25(30.48,0) 26(30.48,2.54) 27(33.02,0) 28(33.02,2.54) 29(35.56,0) 30(35.56,2.54) 31(38.1,0) 32(38.1,2.54) 33(40.64,0) 34(40.64,2.54) 35(43.18,0) 36(43.18,2.54) 37(45.72,0) 38(45.72,2.54) 39(48.26,0) 40(48.26,2.54) 41(50.8,0) 42(50.8,2.54) 43(53.34,0) 44(53.34,2.54) 45(55.88,0) 46(55.88,2.54) 47(58.42,0) 48(58.42,2.54) 49(60.96,0) 50(60.96,2.54)
  silkscreen extent -1.27,-1.27 62.23,3.81
L0603 [mm]
  rect 0.8x0.95 smd mask+0.05: 1(-0.8,0) 2(0.8,0)
  silkscreen extent -1.33,-0.6 1.33,0.6, body extent -0.87,-0.47 0.87,0.47, height 0.95
LED-ARRAY-SMD_4P-L3.5-W2.8-TL [mm]
  rect 1.2x0.95 smd: 1(1.55,0.665) 2(1.55,-0.665) 3(-1.55,-0.665) 4(-1.55,0.665)
  silkscreen extent -1.6,-1.4 1.6,1.4
LM1117-3.3 [mm]
  rect 1.575x0.672 smd: 1(0,0) 2(-2.55,1.598) 3(0,3)
  Top Layer region: -3.64,2.459 -1.785,2.459 -1.741,2.458 -1.696,2.455 -1.652,2.449 -1.608,2.442 -1.565,2.433 -1.522,2.421 -1.479,2.408 -1.437,2.393 -1.396,2.375 -1.356,2.356 -1.317,2.335 -1.279,2.312 -1.241,2.288 -1.206,2.261 -1.171,2.233 -1.138,2.204 -1.106,2.173 -1.075,2.14 -1.047,2.106 -1.019,2.071 -0.994,2.034 -0.97,1.996 -0.948,1.958 -0.928,1.918 -0.91,1.839 0.788,1.839 0.788,1.179 -0.91,1.179 -0.928,1.099 -0.948,1.06 -0.97,1.021 -0.994,0.983 -1.019,0.947 -1.047,0.911 -1.075,0.877 -1.106,0.845 -1.138,0.814 -1.171,0.784 -1.206,0.756 -1.241,0.73 -1.279,0.705 -1.317,0.682 -1.356,0.661 -1.396,0.642 -1.437,0.625 -1.479,0.609 -1.522,0.596 -1.565,0.585 -1.608,0.575 -1.652,0.568 -1.696,0.563 -1.741,0.56 -1.785,0.559 -3.64,0.559 -3.684,0.56 -3.728,0.563 -3.773,0.568 -3.817,0.575 -3.86,0.585 -3.903,0.596 -3.946,0.609 -3.988,0.625 -4.029,0.642 -4.069,0.661 -4.108,0.682 -4.146,0.705 -4.183,0.73 -4.219,0.756 -4.254,0.784 -4.287,0.814 -4.319,0.845 -4.349,0.877 -4.378,0.911 -4.405,0.947 -4.431,0.983 -4.455,1.021 -4.477,1.06 -4.497,1.099 -4.515,1.14 -4.531,1.181 -4.546,1.224 -4.558,1.266 -4.568,1.31 -4.577,1.353 -4.583,1.398 -4.587,1.442 -4.589,1.486 -4.589,1.531 -4.587,1.575 -4.583,1.62 -4.577,1.664 -4.568,1.708 -4.558,1.751 -4.546,1.794 -4.531,1.836 -4.515,1.877 -4.497,1.918 -4.477,1.958 -4.455,1.996 -4.431,2.034 -4.405,2.071 -4.378,2.106 -4.349,2.14 -4.319,2.173 -4.287,2.204 -4.254,2.233 -4.219,2.261 -4.183,2.288 -4.146,2.312 -4.108,2.335 -4.069,2.356 -4.029,2.375 -3.988,2.393 -3.946,2.408 -3.903,2.421 -3.86,2.433 -3.817,2.442 -3.773,2.449 -3.728,2.455 -3.684,2.458
  silkscreen extent -3.01,-0.83 -0.35,3.83
LQFP-48_L7.0-W7.0-P0.50-LS9.0-BL [mm]
  oval 0.27x1.5 smd mask+0.05: 1(-2.75,-4.25) 2(-2.25,-4.25) 3(-1.75,-4.25) 4(-1.25,-4.25) 5(-0.75,-4.25) 6(-0.25,-4.25) 7(0.25,-4.25) 8(0.75,-4.25) 9(1.25,-4.25) 10(1.75,-4.25) 11(2.25,-4.25) 12(2.75,-4.25) 25(2.75,4.25) 26(2.25,4.25) 27(1.75,4.25) 28(1.25,4.25) 29(0.75,4.25) 30(0.25,4.25) 31(-0.25,4.25) 32(-0.75,4.25) 33(-1.25,4.25) 34(-1.75,4.25) 35(-2.25,4.25) 36(-2.75,4.25)
  oval 1.5x0.27 smd mask+0.05: 13(4.25,-2.75) 14(4.25,-2.25) 15(4.25,-1.75) 16(4.25,-1.25) 17(4.25,-0.75) 18(4.25,-0.25) 19(4.25,0.25) 20(4.25,0.75) 21(4.25,1.25) 22(4.25,1.75) 23(4.25,2.25) 24(4.25,2.75) 37(-4.25,2.75) 38(-4.25,2.25) 39(-4.25,1.75) 40(-4.25,1.25) 41(-4.25,0.75) 42(-4.25,0.25) 43(-4.25,-0.25) 44(-4.25,-0.75) 45(-4.25,-1.25) 46(-4.25,-1.75) 47(-4.25,-2.25) 48(-4.25,-2.75)
  silkscreen extent -3.59,-4.46 3.3,3.34
LQFP-100_L14.0-W14.0-P0.50-LS16.0-BL [mm]
  oval 0.3x1.6 smd: 1(-6,-7.55) 2(-5.5,-7.55) 3(-5,-7.55) 4(-4.5,-7.55) 5(-4,-7.55) 6(-3.5,-7.55) 7(-3,-7.55) 8(-2.5,-7.55) 9(-2,-7.55) 10(-1.5,-7.55) 11(-1,-7.55) 12(-0.5,-7.55) 13(0,-7.55) 14(0.5,-7.55) 15(1,-7.55) 16(1.5,-7.55) 17(2,-7.55) 18(2.5,-7.55) 19(3,-7.55) 20(3.5,-7.55) 21(4,-7.55) 22(4.5,-7.55) 23(5,-7.55) 24(5.5,-7.55) 25(6,-7.55) 51(6,7.55) 52(5.5,7.55) 53(5,7.55) 54(4.5,7.55) 55(4,7.55) 56(3.5,7.55) 57(3,7.55) 58(2.5,7.55) 59(2,7.55) 60(1.5,7.55) 61(1,7.55) 62(0.5,7.55) 63(0,7.55) 64(-0.5,7.55) 65(-1,7.55) 66(-1.5,7.55) 67(-2,7.55) 68(-2.5,7.55) 69(-3,7.55) 70(-3.5,7.55) 71(-4,7.55) 72(-4.5,7.55) 73(-5,7.55) 74(-5.5,7.55) 75(-6,7.55)
  oval 1.6x0.3 smd: 26(7.55,-6) 27(7.55,-5.5) 28(7.55,-5) 29(7.55,-4.5) 30(7.55,-4) 31(7.55,-3.5) 32(7.55,-3) 33(7.55,-2.5) 34(7.55,-2) 35(7.55,-1.5) 36(7.55,-1) 37(7.55,-0.5) 38(7.55,0) 39(7.55,0.5) 40(7.55,1) 41(7.55,1.5) 42(7.55,2) 43(7.55,2.5) 44(7.55,3) 45(7.55,3.5) 46(7.55,4) 47(7.55,4.5) 48(7.55,5) 49(7.55,5.5) 50(7.55,6) 76(-7.55,6) 77(-7.55,5.5) 78(-7.55,5) 79(-7.55,4.5) 80(-7.55,4) 81(-7.55,3.5) 82(-7.55,3) 83(-7.55,2.5) 84(-7.55,2) 85(-7.55,1.5) 86(-7.55,1) 87(-7.55,0.5) 88(-7.55,0) 89(-7.55,-0.5) 90(-7.55,-1) 91(-7.55,-1.5) 92(-7.55,-2) 93(-7.55,-2.5) 94(-7.55,-3) 95(-7.55,-3.5) 96(-7.55,-4) 97(-7.55,-4.5) 98(-7.55,-5) 99(-7.55,-5.5) 100(-7.55,-6)
  silkscreen extent -7.03,-8 6.25,6.25
MICRO-USB-SMD_MICROXNJ [mm]
  rect 0.4x1.6 smd paste-100 mask+0.051: 1(-1.3,1.596) 2(-0.65,1.596) 3(0,1.596) 4(0.65,1.596) 5(1.3,1.596)
  round 1.3 hole 0.7: 6(2.425,1.074) 9(-2.425,1.074)
  oval 1.3x1.8 hole 0.7 slot 1.1 at 90 deg: 7(3.625,-1.596) 8(-3.625,-1.596)
  silkscreen extent -3.87,-4.24 3.93,1.71
POWERDI-123_L2.8-W1.8-LS3.7-RD [mm]
  rect 2.4x1.5 smd: 1(-1.187,0)
  rect 1.05x1.5 smd: 2(1.187,0)
  silkscreen extent -2,-1 1.2,1
QFN-24_L4.0-W4.0-P0.50-BL-EP2.6 [mm]
  rect 0.28x0.665 smd paste-100 mask+0.05: 1(-1.25,-1.908) 2(-0.75,-1.908) 3(-0.25,-1.908) 4(0.25,-1.908) 5(0.75,-1.908) 6(1.25,-1.908) 13(1.25,1.908) 14(0.75,1.908) 15(0.25,1.908) 16(-0.25,1.908) 17(-0.75,1.908) 18(-1.25,1.908)
  rect 0.665x0.28 smd paste-100 mask+0.05: 7(1.908,-1.25) 8(1.908,-0.75) 9(1.908,-0.25) 10(1.908,0.25) 11(1.908,0.75) 12(1.908,1.25) 19(-1.908,1.25) 20(-1.908,0.75) 21(-1.908,0.25) 22(-1.908,-0.25) 23(-1.908,-0.75) 24(-1.908,-1.25)
  rect 2.55x2.55 smd paste-100 mask+0.05: 25(0,0)
  silkscreen extent -2.08,-2.61 2.08,2.08
R0603 [mil]
  rect 32x32 smd: 1(-30,0) 2(30,0)
  silkscreen extent -55,-25 54,25
R0805 [mm]
  rect 1.1x1.4 smd: 1(-0.85,0) 2(0.85,0)
  silkscreen extent -1.65,-0.95 1.65,0.95
RES0603 [mil]
  rect 32x32 smd: 1(-30,0) 2(30,0)
  silkscreen extent -55,-25 54,25
RJ45-TH_HR911105A [mm]
  rect 1.6x1.6 hole 1: 1(-4.45,4.355)
  round 1.6 hole 1: 2(-3.18,6.895) 3(-1.91,4.355) 4(-0.64,6.895) 5(0.63,4.355) 6(1.9,6.895) 7(3.17,4.355) 8(4.44,6.895)
  round 1.8 hole 1.1: 9(-6.625,-6.895) 10(-4.085,-6.895) 11(4.085,-6.895) 12(6.625,-6.895)
  round 2.5 hole 1.8: SH1(-7.745,1.055) SH2(7.745,1.055)
  round 3.3 hole 3.3 unplated: ""(-5.715,-1.995) ""(5.715,-1.995)
  silkscreen extent -8.05,-12.92 8.05,8.68
SDM1210P005TF [mm]
  rect 1.485x2.781 smd: 1(-1.524,-0.549) 2(1.676,-0.549)
  silkscreen extent -2.59,-2.2 2.74,1.1
SMD-3225_4P [mm]
  rrect50% 1.4x1.2 smd: 1(-1.1,-0.85)
  rect 1.4x1.2 smd: 2(1.1,-0.85) 3(1.1,0.85) 4(-1.1,0.85)
  silkscreen extent -2.85,-2.45 2.2,1.85
SOP8W_L [mm]
  rect 1.4x0.6 smd: 1(-3.8,1.905)
  oval 1.4x0.6 smd: 2(-3.8,0.635) 3(-3.8,-0.635) 4(-3.8,-1.905) 5(3.8,-1.905) 6(3.8,-0.635) 7(3.8,0.635) 8(3.8,1.905)
  silkscreen extent -3.99,-2.67 2.54,2.74, body extent -3.94,-2.64 3.94,2.64, height 1.9
SOP-8P [mil]
  oval 24x80 smd: 1(-75,-115) 2(-25,-115) 3(25,-115) 4(75,-115) 5(75,115) 6(25,115) 7(-25,115) 8(-75,115)
  silkscreen extent -100,-65 100,65
SOT23 [mm]
  rect 0.8x0.9 smd: 1(0.95,1) 2(-0.95,1) 3(0,-1)
  silkscreen extent -1.45,-0.75 1.45,0.75
SOT23-5 [mil]
  rect 20x50 smd: 1(-37.5,-50) 2(0,-50) 3(37.5,-50) 4(37.5,50) 5(-37.5,50)
  silkscreen extent -50,-15 50,15
SOT23-6 [mm]
  rect 0.55x1 smd: 1(0.95,1.35) 2(0,1.35) 3(-0.95,1.35) 4(-0.95,-1.35) 5(0,-1.35) 6(0.95,-1.35)
  silkscreen extent -1.5,-0.8 1.96,1.52
SOT363 [mm]
  rect 0.35x1 smd: 1(-0.65,-1.1) 2(0,-1.1) 3(0.65,-1.1) 4(0.65,1.1) 5(0,1.1) 6(-0.65,1.1)
  silkscreen extent -1.02,-0.45 1.02,0.45, body extent -1,-1.1 1,1.16, height 1
SOT-23-3_L2.9-W1.3-P1.90-LS2.4-BR [mm]
  rect 1.25x0.7 smd: 1(1,-0.95) 2(1,0.95) 3(-1,0)
  silkscreen extent -0.73,-1.53 0.73,1.53
SWITCH [mm]
  oval 2.5x1 smd: 1(-3.734,2.177) 1(3.835,2.177) 2(-3.734,-2.184) 2(3.835,-2.184)
  silkscreen extent -3.08,-3.1 3.12,3.09, body extent -4.48,-3 4.52,3, height 8.95
TP_SIN [mil]
  rrect60% 50x50 smd: 1(0,0)
USB-A-TH_AF-WJDG [mm]
  round 1.7 hole 1.1: 1(-3.52,1.355) 2(-1.019,1.355) 3(0.98,1.355) 4(3.48,1.355)
  round 3.2 hole 2.3: 5(-6.57,-1.355) 5(6.57,-1.355)
  silkscreen extent -7.2,-11.65 7.2,2.46
USB-C-SMD_KH-TYPE-C-16P [mm]
  oval 1.2x2 hole 0.7 slot 1.7 at 90 deg: 1(-4.32,1.765) 2(4.32,1.765)
  oval 1.2x1.8 hole 0.7 slot 1.4 at 90 deg: 3(-4.32,-2.415) 4(4.32,-2.415)
  rect 0.3x1.3 smd: A1(-3.35,2.415) A4(-2.55,2.415) A5(-1.25,2.415) A6(-0.25,2.415) A7(0.25,2.415) A8(1.25,2.415) A9(2.55,2.415) A12(3.35,2.415) B1(3.05,2.415) B4(2.25,2.415) B5(1.75,2.415) B6(0.75,2.415) B7(-0.75,2.415) B8(-1.75,2.415) B9(-2.25,2.415) B12(-3.05,2.415)
  round 0.7 hole 0.7 unplated: ""(-2.89,1.235) ""(2.89,1.235)
  silkscreen extent -4.57,-5.08 4.57,0.57

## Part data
C1 C3 C6 C15 C35 C37 C54 C55: library part C0805
C2 C4 C5 C16 C18 C23 C25 C26 C27 C28 C29 C30 C31 C32 C33 C34 C36 C38 C39 C40 C41 C42 C43 C44 C45 C46 C47 C48 C49 C50 C51 C52 C53 C58: library part C0603
C7 C8 C9 C10 C11 C12 C13 C14 C17 C19 C20 C21 C22 C24: library part 贴片高压陶瓷电容, "Capacitor (Semiconductor SIM Model)"
C56: library part Cap, "Capacitor"
C57: library part CAP, "Capacitor"
CN3: "Header, 4-Pin, Dual row"
CN4 CN5: "Header, 25-Pin, Dual row"
CN6: "Header, 10-Pin"
CN7 CN8: "Header, 8-Pin"
CN9: "Header, 6-Pin"
D1 D2 D3 D4: Average Rectified Current (Io)=1A, Forward Voltage (Vf@If)=310mV@1A, JLCPCB Part Class="Extended Part", LCSC Part Name="电压:30V 电流:1A", Manufacturer=DIODES(美台), Reverse Voltage (Vr)=30V
ETH: library part HR911105A_C12074, Manufacturer=HANRUN
FUSE1: library part SMD1210P005TF, "https://item.szlcsc.com/947797.html?fromZone=s_s__%25226V%2520500mA%2522"
JP4 JP5: library part CON2_DIP
K1 K2 K3: BOM_JLCPCB Part Class="Extended Part", BOM_Manufacturer=HYP, BOM_Manufacturer Part=1TS002B-2600-5001_KEY
L1 L2: "SMD Chip ferrite bead, 600R@100MHz +/-25%, 350mA, 500mohm DC, 0603, T=0.8mm", Manufacturer=TAI-TECH, Manufacturer_Part_Number=FCM1608KF-601T03
L3 L4 R1 R2 R3 R4 R5 R6 R7 R8 R9 R10 R11 R12 R13 R14 R16 R17 R18 R19 R20 R21 R22 R23 R24 R25 R26 R27 R28 R29 R30 R31 R32 R33 R34 R35 R36 R37 R38 R39 R40 R41 R42 R43 R44 R45 R46 R47 R48 R49 R50 R51 R52 R53 R54 R55 R56 R57 R58 R59 R60 R61 R62 R63 R64 R65 R66 R67 R68 R69 R70 R71 R72 R73 R74 R75 R76 R77 R78 R79 R80 R81 R82 R83 R84 R85 R86 R87 R88 R89 R90 R91 R92 R93 R94 R95 R96 R98 R99 R100 R101 R102 R103 R104 R105 R106 R107 R108 R109 R110 R111 R112: library part R0603
LED1: JLCPCB Part Class=扩展库, LCSC Part Name=RGB三色, Manufacturer=MEIHUA(美华)
LED2 LED3: library part PDI-E803_Dup1
Q1: library part "MOSFET N", "MOSFET N"
Q2 Q3: library part SI2301_C181086, Continuous Drain Current (Id)=2.3A, Drain Source On Resistance (RDS(on)@Vgs,Id)=120mΩ@4.5V,2.8A, Drain Source Voltage (Vdss)=20V, Gate Threshold Voltage (Vgs(th)@Id)=1V@250uA, JLCPCB Part Class="Extended Part", LCSC Part Name="P沟道 耐压:20V 电流:2.3A", Manufacturer=Hottech(合科泰), Power Dissipation (Pd)=1.25W
R15 R97: library part R0805
U3 U4: library part ESDALC6V1W5, "Dual Transil array for ESD protection", Manufacturer=STMICROELECTRONICS
U11 U19 U20: "ESD protection 6V1", Manufacturer=STMICROELECTRONICS, Manufacturer_Part_Number=ESDALC6V1-1U2
U15: "LQFP48", BOM_Manufacturer=PUYA(普冉)
U17: library part SST25VF010, "SST25VF010"
U18: "LQFP100", BOM_Manufacturer=PUYA(普冉)
U21: library part W25Q256, "外置flash"
U22: "立创 C45223", JLCPCB Part Class="Extended Part", Manufacturer=MICROCHIP(美国微芯), Operating Temperature=0℃~+85℃, Supply Voltage=1.6V~3.6V
USB: BOM_JLCPCB Part Class="Extended Part", BOM_Manufacturer="Shenzhen Kinghelm Elec"
USB1 USB2: library part MicroXNJ, Current Rating - Power (Max)=1A, JLCPCB Part Class="Extended Part", LCSC Part Name="Micro-B 母 卧贴", Manufacturer="SHOU HAN(首韩)", Operating Temperature Range=-20℃~+85℃
USB1_HOST: library part "AF 90° WJDG", Current Rating - Power (Max)=1.5A, JLCPCB Part Class="Extended Part", LCSC Part Name="Type-A 母 弯插", Manufacturer="SHOU HAN(首韩)", Operating Temperature Range=-25℃~+85℃
Y1 Y2: library part ABM8AIG-24.000MHZ-82Z-T, "±20ppm , 12.5pF , T_use: -40°C~125°C", Equivalent Series Resistance (ESR)=50Ω, External load capacitor=8pF, Frequency Stability(Full temperature range)=±50ppm, JLCPCB Part Class="Extended Part", LCSC Part Name="24MHz ±20ppm 8pF", Manufacturer=ABRACON, Normal temperature Frequency Tolerance=±20ppm, Operating Temperature=-40℃~+125℃
Y3: library part XKXGI-SUA-32.768K, "±20ppm , 12.5pF , T_use: -40°C~125°C", External load capacitor=12.5pF, Frequency Stability(Full temperature range)=±30ppm, JLCPCB Part Class="Extended Part", LCSC Part Name="32.768kHz ±20ppm 12.5pF YST310S", Manufacturer=YXC(扬兴晶振), Normal temperature Frequency Tolerance=±20ppm, Operating Temperature=-40℃~+85℃
Y4: library part 12MHz, BOM_LCSC Assembly=Yes, BOM_Manufacturer=TAE, BOM_Manufacturer Part=SMD-3225_4P12M20pf10ppm

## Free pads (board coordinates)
  round 137.8 hole 125.98: 0(965.02,2533.76) 0(969.33,-4.92) 0(4148,-39.3) 0(4148,2568.14)
  round 125.98 hole 125.98 unplated: 0(1560.11,316.55) 0(1610.11,2216.55) 0(3610.11,1616.55)

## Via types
v1: diameter 22, hole 12, Top Layer to Bottom Layer, tented both sides, 398 vias
v2: diameter 16, hole 8, Top Layer to Bottom Layer, tented both sides, 111 vias
v3: diameter 20, hole 10, Top Layer to Bottom Layer, tented both sides, 54 vias
v4: diameter 16, hole 9, Top Layer to Bottom Layer, tented both sides, 41 vias
v5: diameter 30, hole 15, Top Layer to Bottom Layer, tented both sides, 15 vias
v6: diameter 20, hole 10, Top Layer to Bottom Layer, 9 vias
v7: diameter 15, hole 8, Top Layer to Bottom Layer, tented both sides, 5 vias
v8: diameter 16, hole 8, Top Layer to Bottom Layer, 3 vias
v9: diameter 20, hole 12, Top Layer to Bottom Layer, tented both sides, 1 vias

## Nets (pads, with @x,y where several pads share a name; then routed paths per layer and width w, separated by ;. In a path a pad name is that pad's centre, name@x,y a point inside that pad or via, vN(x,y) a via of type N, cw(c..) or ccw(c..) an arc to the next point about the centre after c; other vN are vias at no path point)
3.3V_OUT_EN: R23.1 U15.46 | length 821.7
  Top Layer w6: U15.46@88.18,1106.6 88.82,1107.24 126.39,1107.24 137.81,1118.66 v4(137.81,1139.74) ; v4(405,1735) 405,1770 R23.1@405.5,1770.5
  Bottom Layer w6: v4(137.81,1139.74) 132.55,1145 132.55,1167.65 405,1440.09 v4(405,1735)
3V3: C55.2 C56.2 CN7.4 JP4.1 U23.2 | length 355.6
  Top Layer w30: U23.2@1543.38,844.2 1543.38,976.71 C55.2@1538,982.09 1538,1102.09 JP4.1@1605.5,1169.59
3V3_PYLK: C1.2 C2.2 C7.2 C8.2 C9.2 C10.2 C17.2 C19.2 C20.2 C21.2 C22.2 CN2.1 LED1.1 R14.2 R26.1 R34.2 R35.2 U1.1 U2.1 U5.1 U7.1 U8.1 U9.2 U10.1 U12.1 U13.5 U14.1 U15.9 U15.24 U15.48 U17.3 U17.7 U17.8 | length 3645.5
  Top Layer w11: U15.9@304.71,1008.18 304.71,971.07 430.5,845.28 C21.2@430.5,806.5 ; 400.22,878.06 439.59,917.43 v1(439.59,919.91)
  Top Layer w12: U7.1@-43.78,515.38 -21.19,492.79 47.4,492.79 136.82,492.79 ; 46.56,493.63 U8.1@46.56,531.35 ; U10.1@136.82,531.26 136.82,492.79 ; C7.2@207.6,624.9 227.25,605.25 U5.1@227.25,531.35 227.25,510.19 209.85,492.79 136.82,492.79 ; U2.1@317.59,531.35 317.59,503.28 331.87,489 386.52,489 407.93,510.42 U12.1@407.93,531.35 ; U14.1@588.62,531.35 588.62,577.71 C8.2@647,636.09 685,636.09 v1(687,638.09) ; R35.2@648,1013 685.6,1013 v1(686.1,1012.5)
  Top Layer w15: v1(-197,725.89) -196.61,725.5 R26.1@-149.5,725.5 ; v1(-158.9,776.09) -131.59,776.09 -88.5,819.19 C22.2@-88.5,825.5 -74.09,825.5 66.9,966.49 66.9,1067.23 U15.48@88.18,1067.23 ; C20.2@-150.5,675.5 R26.1@-150.5,724.5 ; LED1.1@-145.69,2511.52 v1@-145.69,2565.2 ; U7.1@-43.78,515.38 U7.1@-43.78,531.35 ; C9.2@46.3,624.9 46.56,624.64 U8.1@46.56,531.35 ; R14.2@80.5,2105.5 80.5,2150.82 v1(80.72,2151.04) ; v1(206.64,648.09) 206.76,647.97 206.76,635.94 212.7,630 C7.2@207.6,624.9 ; U15.24@400.85,1285.9 434.6,1285.9 v1(456.5,1307.8) 518,1369.3 C19.2@585,1369.3 ; U12.1@407.93,531.35 407.93,623.47 C10.2@406.5,624.9 425.31,624.9 v1(440.19,639.78) ; U1.1@498.28,531.35 498.28,516.52 522.11,492.68 573.14,492.68 588.62,508.16 U14.1@588.62,531.35
  Top Layer w25: v1(-145.96,2565.48) v1@-145.69,2565.2 ; U17.3@-139.3,1242.5 -139.3,1106.86 -89.3,1056.86 U17.7@-89.3,1012.5 U17.8@-39.3,1012.5 ; C2.2@380.5,2044.5 443,2044.5 455.5,2032 C1.2@455.5,2030.5 C1.2@460.88,2025.12
  Top Layer w30: U13.5@230.5,1875.5 230.5,1919.49 267.73,1956.72 400.16,1956.72 ; C1.2@460.88,2025.12 U9.2@592.6,2025.12
  Bottom Layer w12: v1(456.5,1307.8) 466.1,1307.8 642,1131.9 642,1056.6 v1(686.1,1012.5)
  Bottom Layer w25: C17.2@-138,1088 -138.75,1088.75 v1(-138.75,1125.3) -139.21,1125.76 -139.21,1160.79 R34.2@-137,1163
  other v1: 434.3,1933.2 381.6,1937.1 469.5,1968.5 415.3,1972.4 364.5,1985.6
3V3_USB_PYLK: C6.2 JP1.1 U13.1 | length 609.7
  Top Layer w25: U13.1@230.5,1775.5 230.5,1725.08 280.08,1675.5 280.5,1675.5 293,1663 293,1654.21 305.5,1641.71 334.74,1641.71 389.5,1586.96 389.5,1521.63 435.63,1475.5 JP1.1@643,1475.5
5V: C54.2 C57.2 CN3.2 CN7.5 D1.1 D2.1 D3.1 D4.1 Q2.2 Q3.2 R83.2 R91.2 U23.3 USB1_HOST.1 | length 1518.7
  Top Layer w25: C54.2@1443,662.09 C54.2@1460.5,644.59 ; C57.2@1443,717.09 C57.2@1445.5,719.59
  Top Layer w30: R83.2@4380.5,577.09 4426.9,577.09 4434.3,569.69 ; R91.2@4380.5,814.59 4428.35,814.59 v5(4428.74,814.2) 4429.14,814.59 4471.23,814.59 Q3.2@4478.63,807.19 ; Q2.2@4478.63,569.69 4434.3,569.69 ; USB1_HOST.1@4503.65,26.49 4457.75,26.49 4379.24,105 4379.24,467.84 v5(4435,523.59) 4434.3,524.29 4434.3,569.69
  Top Layer w60: D1.1@1327.25,907.09 D2.1@1327.25,819.59 D4.1@1327.25,732.09 D3.1@1327.25,644.59 1393.88,644.59 ; v5@1393.88,524.52 1393.88,644.59 ; C54.2@1443,662.09 1443,717.09 U23.3@1443,788.98 ; C54.2@1460.5,644.59 1393.88,644.59
  other v5: 1396.39,522.01
5V_OUT_EN: R28.1 U15.11 | length 930.4
  Top Layer w6: U15.11@344.08,1008.18 U15.11@344.08,1008.37 344.08,1068.17 347.88,1071.97 v4(347.88,1074.67) ; v4(592.5,1688.59) 652.92,1749.01 652.92,1767.92 R28.1@655.5,1770.5
  Bottom Layer w6: v4(347.88,1074.67) 347.88,1154.99 300.71,1202.16 300.71,1276.81 592.5,1568.59 v4(592.5,1688.59)
5V_USB1_START: 5V_USB1.1 D3.2 Q2.3 R89.2 USB1.1 | length 898.3
  Top Layer w6: R89.2@4385.5,694.59 4509.58,694.59 4563.66,640.52 v5(4562.72,639.58)
  Top Layer w15: 5V_USB1.1@4487.04,973.85 4499.03,961.86 v3(4499.03,924.39)
  Top Layer w25: D3.2@1219.55,630.39 D3.2@1233.75,644.59 ; v5(4562.72,639.58) 4562.72,614.32 Q2.3@4563.66,613.38 ; v1(4739.6,712.69) USB1.1@4765.65,738.74
  Top Layer w30: v5(1179.7,630.39) D3.2@1219.55,630.39
  Bottom Layer w15: v3(4499.03,924.39) 4498.7,924.06 4498.7,703.6 v5(4562.72,639.58)
  Bottom Layer w25: v5(4562.72,639.58) 4564.2,641.07 4667.97,641.07 v1(4739.6,712.69)
5V_USB2_START: 5V_USB2.1 D4.2 Q3.3 R96.2 USB2.1 | length 734.8
  Top Layer w6: v5(1175.3,732.79) v5@1176,732.09
  Top Layer w15: 5V_USB2.1@4479.3,1078.69 4519.18,1038.81 4557.37,1038.81
  Top Layer w25: v5(4547.58,803.83) 4557.37,813.63 Q3.3@4557.37,844.59 4557.37,1038.81 USB2.1@4770.08,1251.52
  Top Layer w30: v5@1176,732.09 D4.2@1233.75,732.09
  Bottom Layer w6: R96.2@2122.8,707.59 R96.2@2124.2,706.19
  Bottom Layer w15: v2(2083.7,708.99) 2085.1,707.59 R96.2@2122.8,707.59
5V_USB_CHGR: 5V_USB.1 C3.2 C4.2 FUSE1.2 U9.3 U16.5 | length 771.5
  Top Layer w15: 5V_USB.1@396.1,2274.79 534.79,2274.79 537.39,2277.39 C3.2@548,2288
  Top Layer w30: U16.5@480.5,1875.5 480.5,1888.6 v5(518.78,1926.88) ; U9.3@537.39,2125.5 C3.2@537.39,2277.39 ; C3.2@548,2288 556.89,2296.89 556.89,2370.28 571.12,2384.52 FUSE1.2@596.39,2384.52
  Bottom Layer w30: v5(518.78,1926.88) 537.08,1945.18 v5(537.08,2182.9)
5V_USB_PYLK: C15.2 D1.2 JP1.3 U16.1 | length 2053.4
  Top Layer w25: C15.2@468,1658 C15.2@480.5,1658
  Top Layer w30: C15.2@468,1658 474.98,1664.98 U16.1@474.98,1785.62 ; C15.2@480.5,1658 625.5,1658 JP1.3@643,1675.5 643,1675.9 699.2,1732.09 699.2,1925.85 729.39,1956.04 801.05,1956.04 843,1914.09 843,1657.09 899.21,1600.88 1111.79,1600.88 1184.47,1528.2 1184.47,956.38 D1.2@1233.75,907.09
AD_TVDD: R16.1 R20.2 U15.19 | length 200
  Top Layer w6: U15.19@422.82,1185.34 R20.2@572.84,1185.34 ; R20.2@588,1188 R16.1@588,1238
DIR_RESET: U10.5 U15.3 | length 771.5
  Top Layer w6: v3@-9.1,703.47 -9.1,778.02 186.6,973.72 U15.3@186.6,1008.37 ; v3@110.4,399.79 111.31,400.71 U10.5@111.31,444.73
  Bottom Layer w6: v3(-8.68,698.63) 8.38,681.57 8.38,510.32 v3(110.8,407.89)
DIR_RTCK_DTR: U5.5 U15.4 | length 840.5
  Top Layer w6: v3@16.8,746.13 16.8,780.3 206.29,969.79 U15.4@206.29,1008.37 ; v3@200.9,405.19 201.28,405.57 201.28,444.36 U5.5@201.66,444.73 U5.5@201.66,463.18
  Bottom Layer w6: v3(18,744.79) 24.43,738.36 24.43,533.26 103.3,454.39 158.5,454.39 v3(201.3,411.59)
DIR_TCK_SWCLK: U2.5 U15.21 | length 1201.9
  Top Layer w6: v4(288.97,487.38) 292,484.35 U2.5@292,444.73 ; v4(311.14,1156.92) 311.14,1158.68 377.17,1224.71 U15.21@422.82,1224.71
  Bottom Layer w6: v4(288.97,487.38) 287.69,486.09 109.4,486.09 40.65,554.84 40.65,930.45 267.13,1156.92 v4(311.14,1156.92)
DIR_TDI_VCP_TX: U12.5 U15.20 | length 923.6
  Top Layer w6: v4(370.66,1189.06) 386.83,1205.22 U15.20@422.63,1205.22 ; U12.5@382.34,444.73 382.34,462.04 406.1,485.79 v4@416.2,485.79
  Bottom Layer w6: v4(370.66,1189.06) 513.86,1045.86 513.86,758.09 415.58,659.81 v4(415.58,485.18)
DIR_TDO_SWO: U7.5 U15.43 | length 905.8
  Top Layer w6: v4(-72.3,482) -70.84,480.54 -70.84,446.2 U7.5@-69.37,444.73 ; U15.43@88.37,1165.85 160.54,1165.85 v4(176.8,1149.59)
  Bottom Layer w6: v4(-72.3,482) -74.03,483.73 -74.03,869.81 176.8,1120.64 v4(176.8,1149.59)
DIR_TMS_SWDIO: U1.5 U15.14 | length 782.4
  Top Layer w6: U15.14@422.82,1086.92 479.5,1086.92 518,1048.42 518,684 428.46,594.46 428.46,503.7 443.39,488.77 464.24,488.77 472.69,480.32 U1.5@472.69,444.73
DIR_TRST_RTS: U8.5 U15.2 | length 765
  Top Layer w6: v3(-47.6,761.69) 166.92,976.21 U15.2@166.92,1008.37 ; U8.5@20.97,444.73 20.97,404.42 v3@21.14,404.26
  Bottom Layer w6: v3(-47.6,761.69) -55.3,753.99 -55.3,504.39 20.9,428.19 v3(20.9,407.49)
DIR_VCP_RX: U14.5 U15.22 | length 1486.9
  Top Layer w6: v4(284.56,1124.93) 284.56,1163.3 365.66,1244.4 U15.22@422.82,1244.4 ; v4(563.03,408.08) U14.5@563.03,444.73
  Bottom Layer w6: v4(284.56,1124.93) 259.03,1124.93 56.81,922.7 56.81,565.69 86.8,535.69 330.6,535.69 441.3,424.99 546.11,424.99 v4(563.03,408.08)
E_5V: CN11.1 D2.2 | length 2248
  Top Layer w30: v5(907.01,841.78) 929.2,819.59 D2.2@1233.75,819.59
  Bottom Layer w30: v5(907.01,841.78) 843,905.79 843,1994.59 1283.95,2435.55 CN11.1@1393.11,2435.55
ESMC_CLK: R44.1 R51.1 U21.6 | length 1883.4
  Top Layer w6: U21.6@1368,1456.7 1368,1440.83 1399.02,1409.81 v2(1561.29,1409.81)
  Bottom Layer w6: v2(1561.29,1409.81) 1871.14,1719.66 2312.45,1719.66 2417,1615.11 2417,1396.7 ; R51.1@2205,1109.3 2417,1321.3 2417,1396.7 ; R44.1@2456.1,1399.9 2420.2,1399.9 2417,1396.7
ESMC_CS: R43.1 R50.1 R90.1 U21.1 | length 2156.5
  Top Layer w6: U21.1@1268,1157.49 1276.81,1166.3 1276.81,1182.05 1277.72,1182.05 1308.51,1212.84 v2(1322.71,1212.84)
  Bottom Layer w6: R90.1@1292.5,1212.5 1292.84,1212.84 v2(1322.71,1212.84) 1847.2,1737.33 2317.84,1737.33 2531.43,1523.74 2531.43,1429.13 2495.9,1393.6 2495.9,1370.9 2263.99,1138.99 2263.99,1118.99 R43.1@2262.5,1117.5 ; R43.1@2258.5,1110.3 R43.1@2258.5,1117.5
ESMC_IO0: R47.1 R52.1 U21.5 | length 1938.3
  Top Layer w6: U21.5@1418,1467.68 1423.2,1472.88 1438.16,1472.88 v7(1439.88,1474.6)
  Bottom Layer w6: v7(1439.88,1474.6) 1773.28,1807.99 2336.1,1807.99 2596.44,1547.65 2596.44,1362.94 2521.2,1287.7 2521.2,1115.5 2519.7,1114 R47.1@2474.1,1114
ESMC_IO1: R46.1 R53.1 U21.2 | length 2164.6
  Top Layer w6: U21.2@1318,1157.49 1321.38,1160.86 1321.38,1175.88 1351.22,1205.72 v2(1351.22,1277.54)
  Bottom Layer w6: v2(1351.22,1277.54) 1351.22,1278.61 1827.6,1754.99 2323.65,1754.99 2446.01,1632.63 2548.99,1529.65 2548.99,1389.29 2362.5,1202.8 R46.1@2362.5,1117.5 ; R53.1@2312.5,1110.4 2363.7,1110.4 R46.1@2364.2,1109.9
ESMC_IO2: R48.1 R55.1 U21.3 | length 2131.3
  Top Layer w6: U21.3@1368,1157.49 1368,1175.68 1377.89,1185.56 v2(1377.89,1374.34)
  Bottom Layer w6: R48.1@1292.5,1362.5 1304.34,1374.34 v2(1377.89,1374.34) 1793.87,1790.33 2331,1790.33 2580.18,1541.15 2580.18,1372.88 2475.99,1268.69 2475.99,1243.49 R55.1@2475,1242.5
ESMC_IO3: R49.1 R56.1 U21.7 | length 2192.8
  Top Layer w6: U21.7@1318,1456.7 1321.37,1453.33 1321.37,1439.13 1365.81,1394.69 1418.36,1394.69 1423.57,1389.48 v2(1426.28,1389.48)
  Bottom Layer w6: R49.1@1292.5,1312.5 1346.83,1312.5 1423.81,1389.48 v2(1426.28,1389.48) 1809.46,1772.66 2326.91,1772.66 2564.17,1535.4 2564.17,1381.95 2413.8,1231.58 R56.1@2413.8,1109.9
ETH_VDD: C40.2 C49.2 ETH.4 ETH.5 L3.2 R97.2 U22.9 | length 552.8
  Top Layer w6: R97.2@4280.5,1274.59 R97.2@4281.5,1275.59 ; C49.2@4330.5,1275.59 C49.2@4331.5,1274.59 ; v5(4471.1,1274.59) v5@4474.1,1277.59
  Top Layer w11: C49.2@4323.66,1284.25 U22.9@4323.66,1389.49
  Top Layer w25: R97.2@4281.5,1275.59 C49.2@4330.5,1275.59 ; C49.2@4331.5,1274.59 L3.2@4380.5,1274.59 v5(4471.1,1274.59)
  Bottom Layer w6: C40.2@4594.5,2182.09 4594.5,2053.33 ETH.5@4596.19,2051.64 4596.19,2001.64 ETH.4@4646.19,1951.64
ETH_VDDA: C45.2 C46.2 C47.2 C48.2 L3.1 R98.2 R99.2 R100.2 R101.2 U22.1 U22.19 | length 881.2
  Top Layer w15: v5(3969.15,1703.22) 4008.87,1703.22 C48.2@4016.2,1695.89 4076,1695.89 C47.2@4076.7,1695.19 4239.14,1532.75 4239.45,1532.75 U22.1@4258.4,1513.8 ; R98.2@4204.4,1689.59 4204.4,1662.2 v9(4204.46,1662.15) ; L3.1@4380.5,1214.59 4396.3,1214.59 v1(4433.3,1177.59) ; U22.19@4386.25,1536.16 4568.94,1536.16 C45.2@4578,1527.09 4578,1532.82 C46.2@4578,1577.09 4578,1612.39 v1(4578.4,1612.79) ; v1@4423.8,1665.92 v1(4424.02,1665.69) ; R101.2@4639.4,1689.59 4685.2,1689.59 v1(4686.4,1688.39)
  Top Layer w25: R99.2@4389.4,1689.59 4423.8,1689.59 ; v1@4423.8,1665.92 4423.8,1689.59 ; R100.2@4454.4,1689.59 4423.8,1689.59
